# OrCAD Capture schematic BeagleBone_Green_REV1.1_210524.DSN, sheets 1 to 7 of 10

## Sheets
1 P01_Title Page: title: BeagleBone Green Cover Page; rev: v1
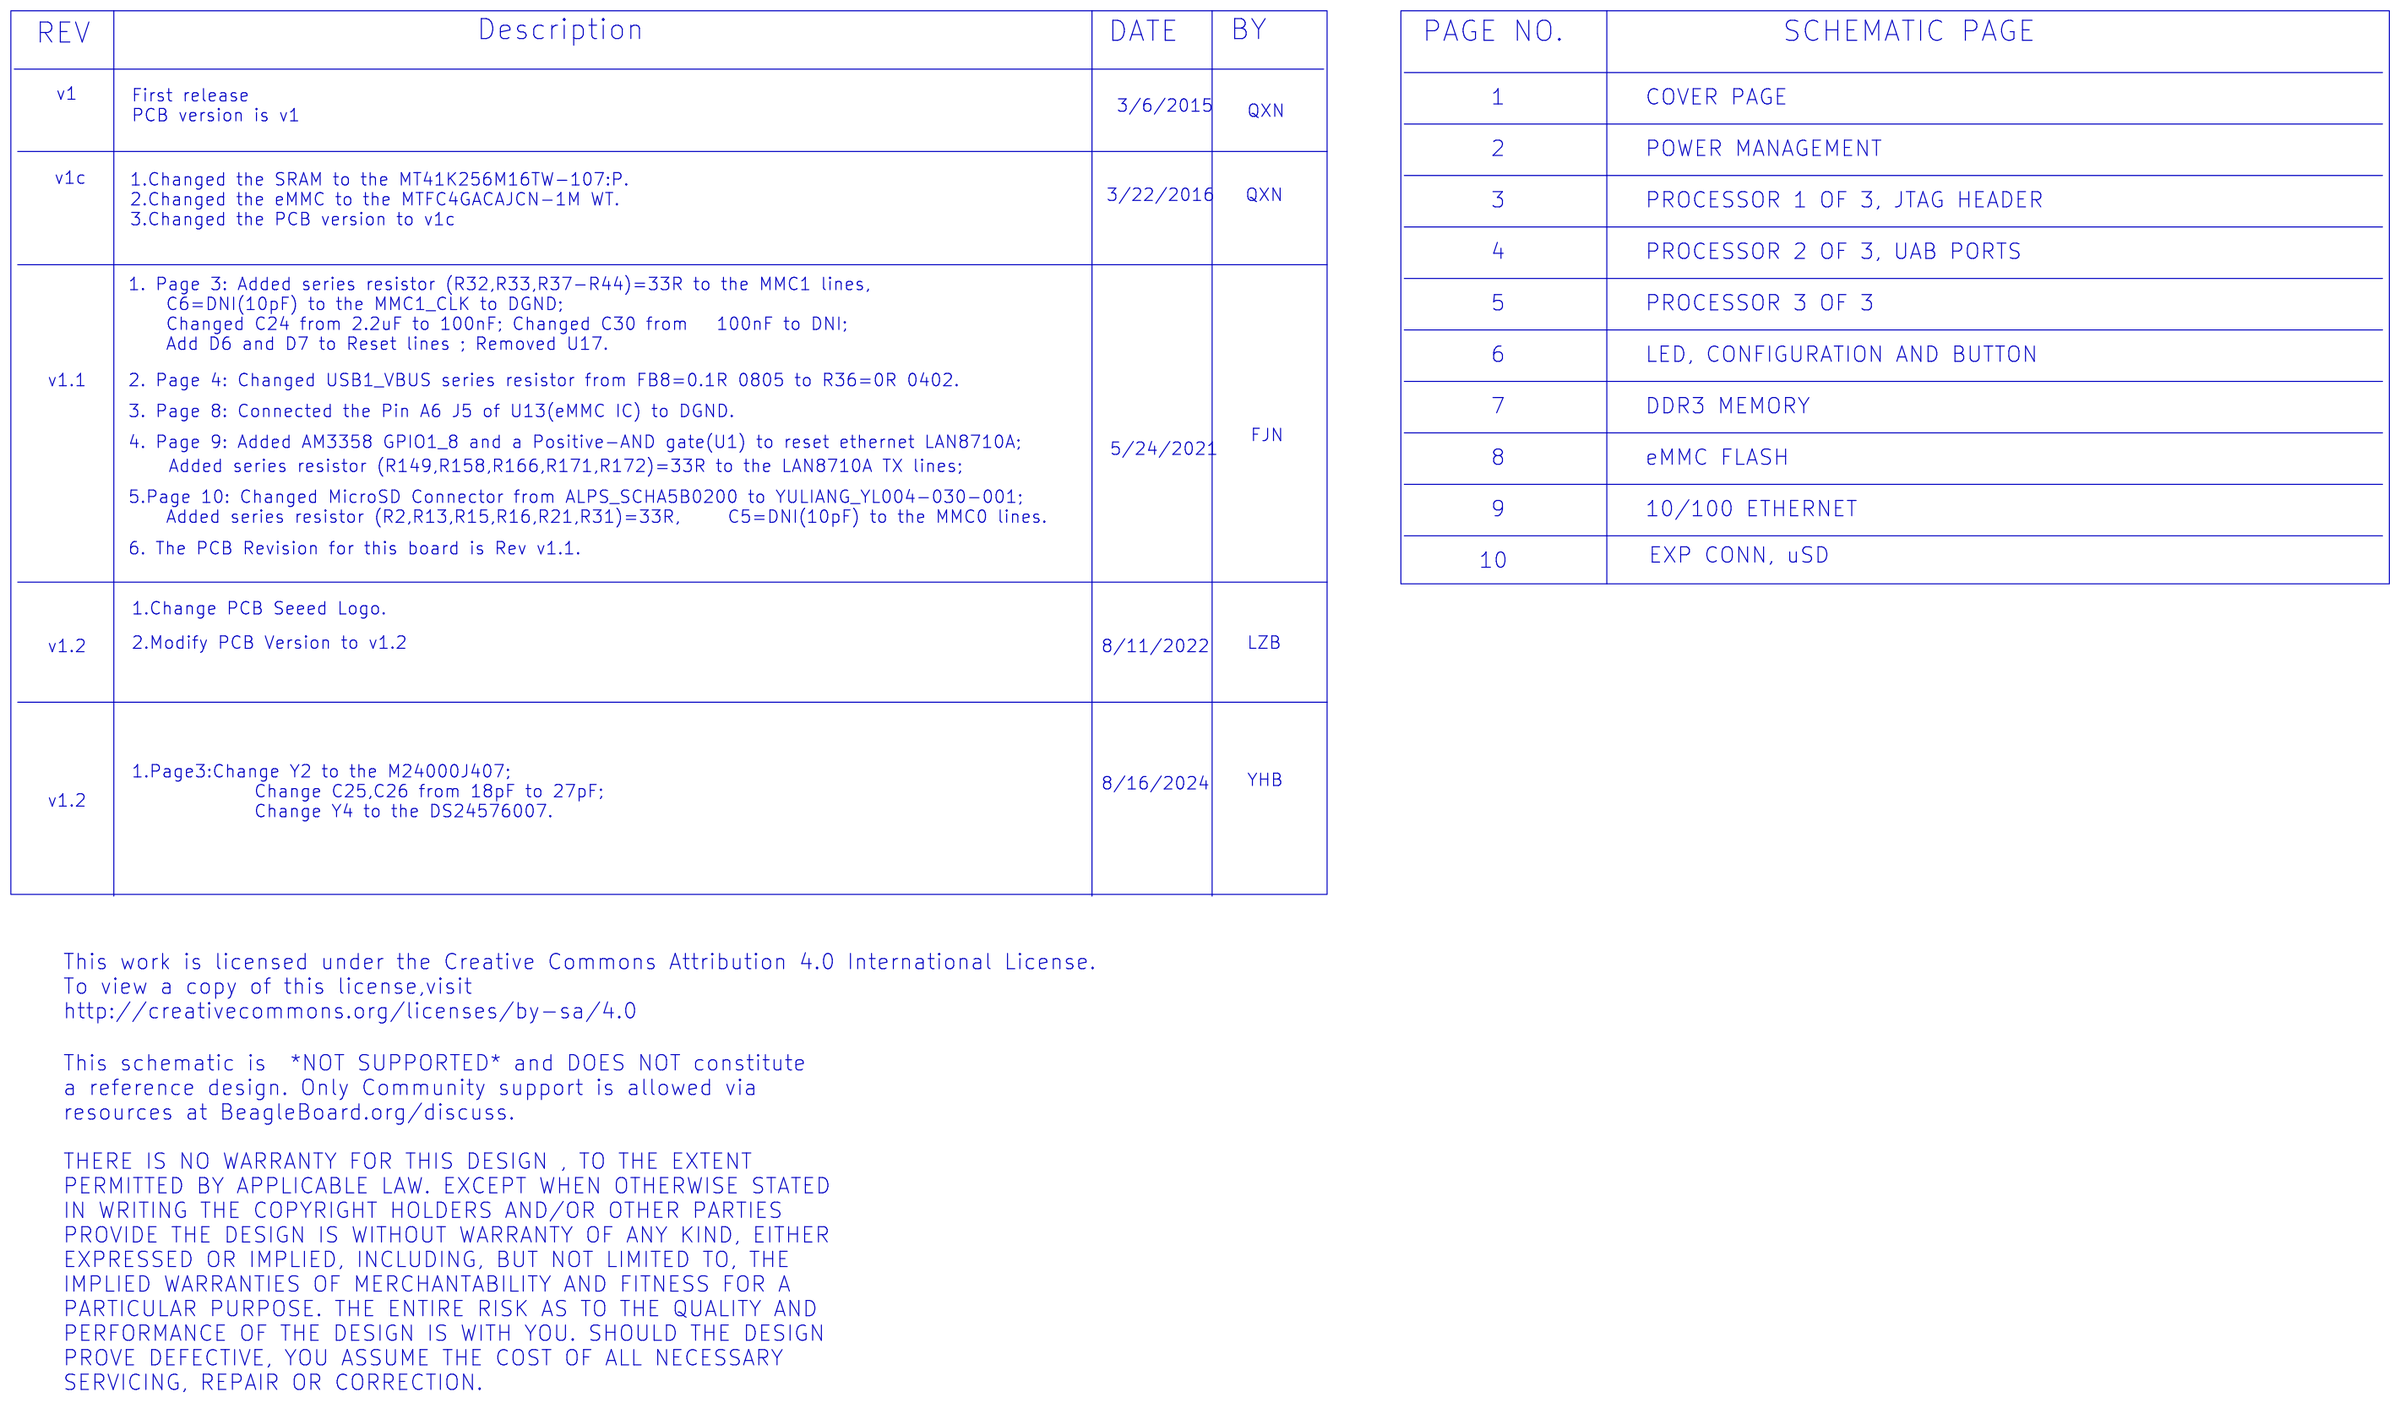
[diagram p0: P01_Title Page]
2 P02_Power Management: size B; title: BeagleBone Green Power Management
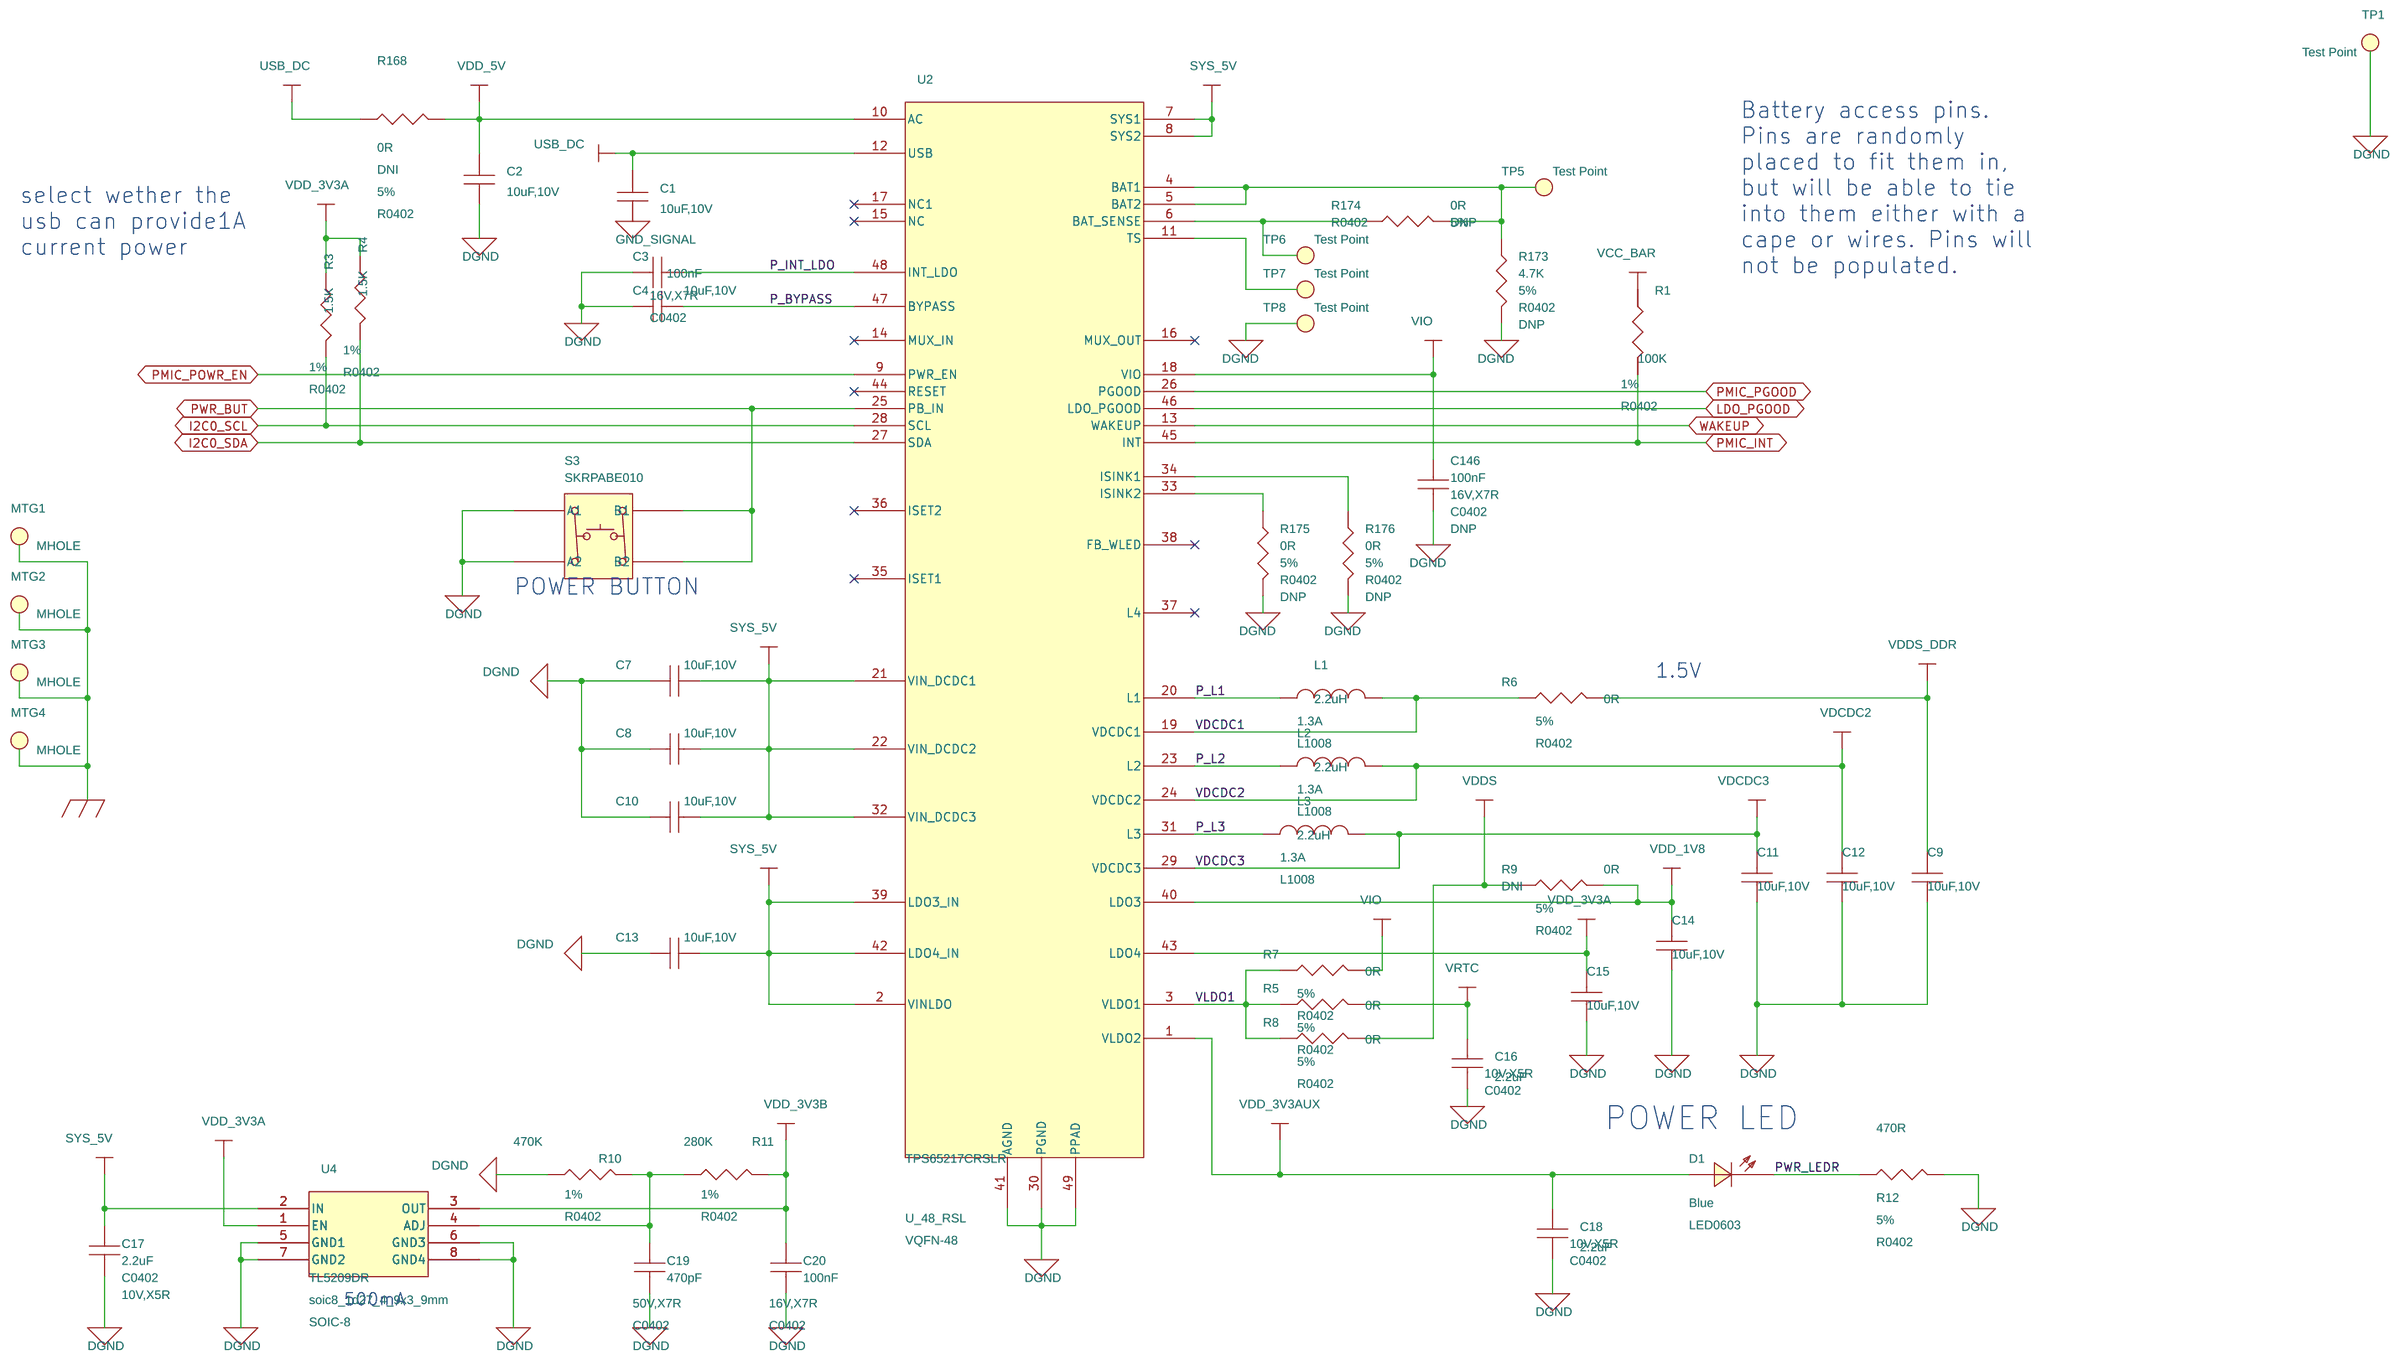
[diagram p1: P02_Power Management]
3 P06_LED, Config: size B; title: BeagleBone Green LED, Configuration, and Reset
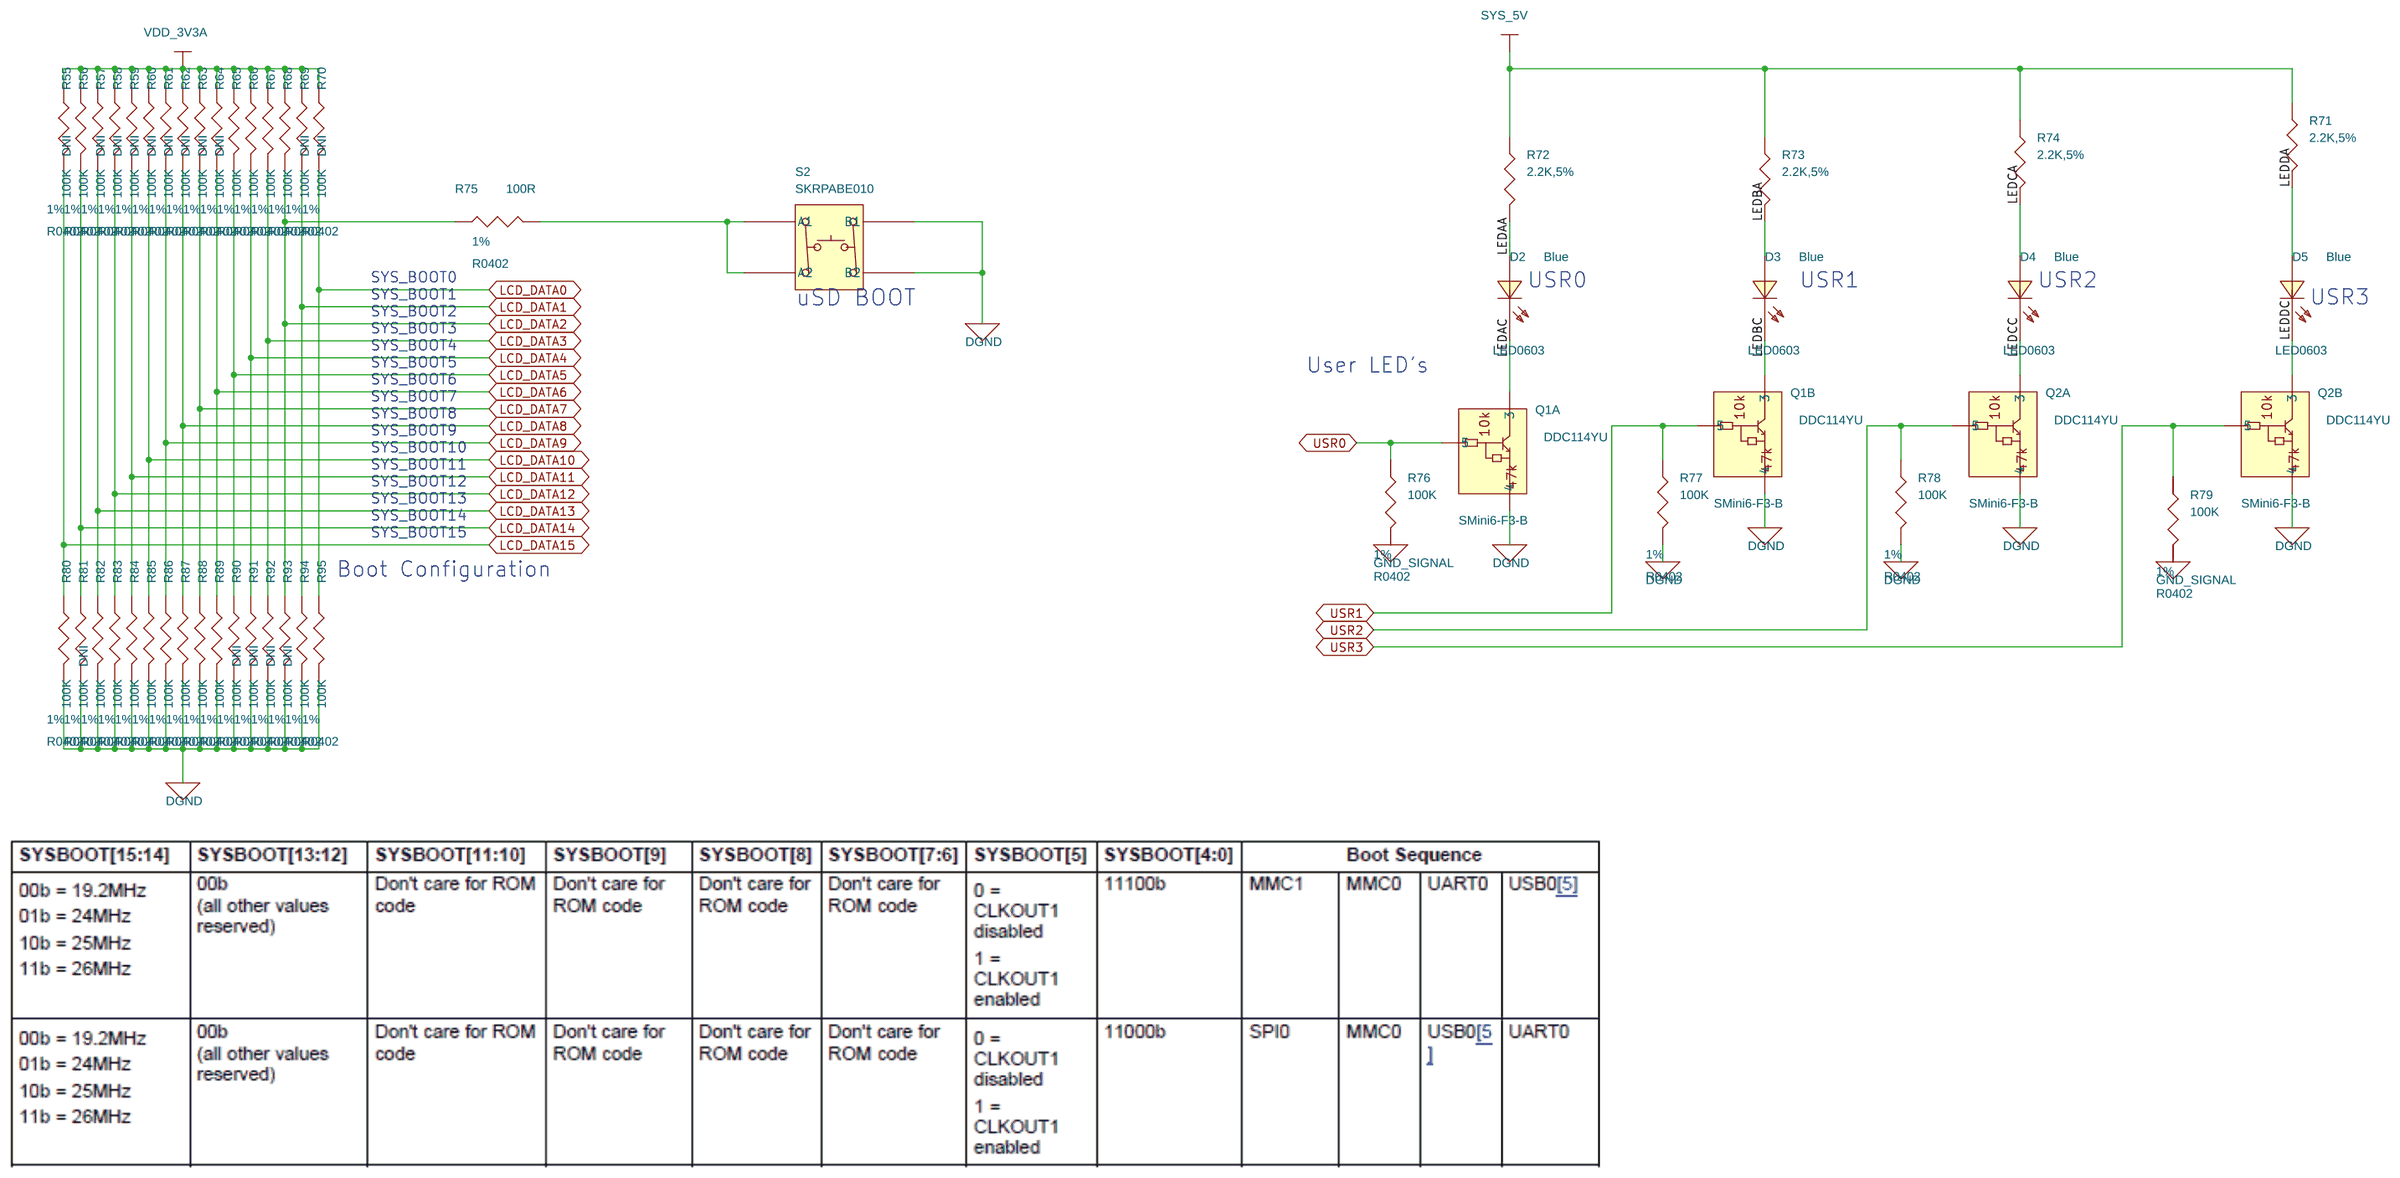
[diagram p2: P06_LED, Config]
4 P07_DDR3 Memory: size B; title: BeagleBone Green DDR3 Memory
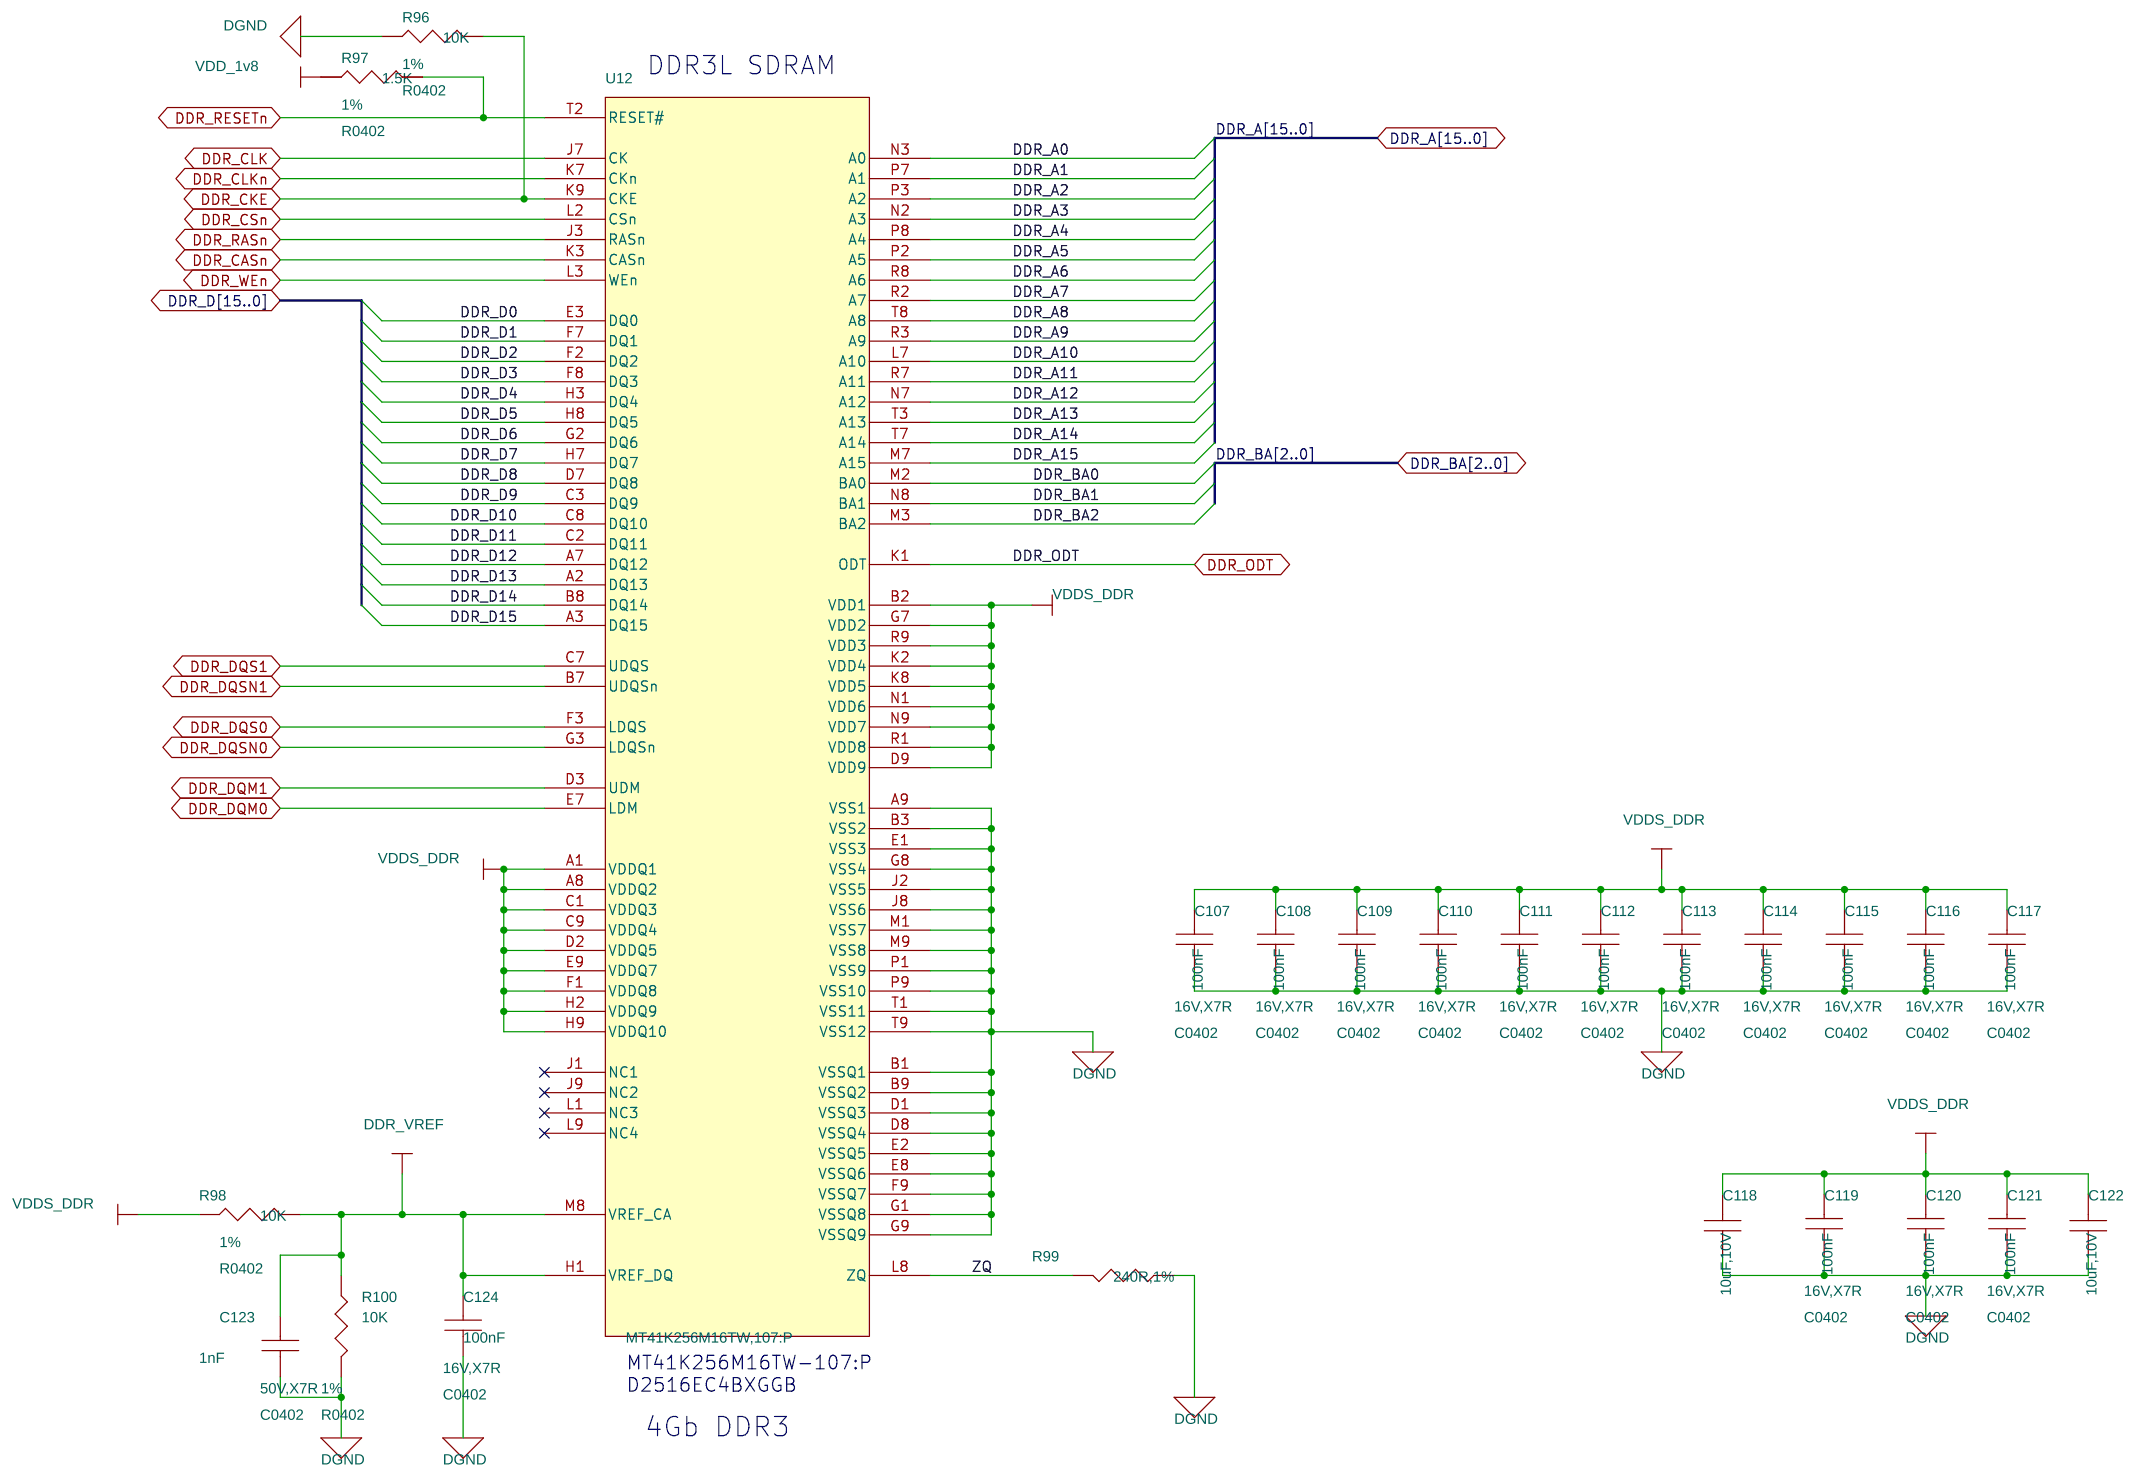
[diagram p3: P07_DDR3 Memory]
5 P08_eMMC FLASH: size B; title: BeagleBone Green 4G eMMC
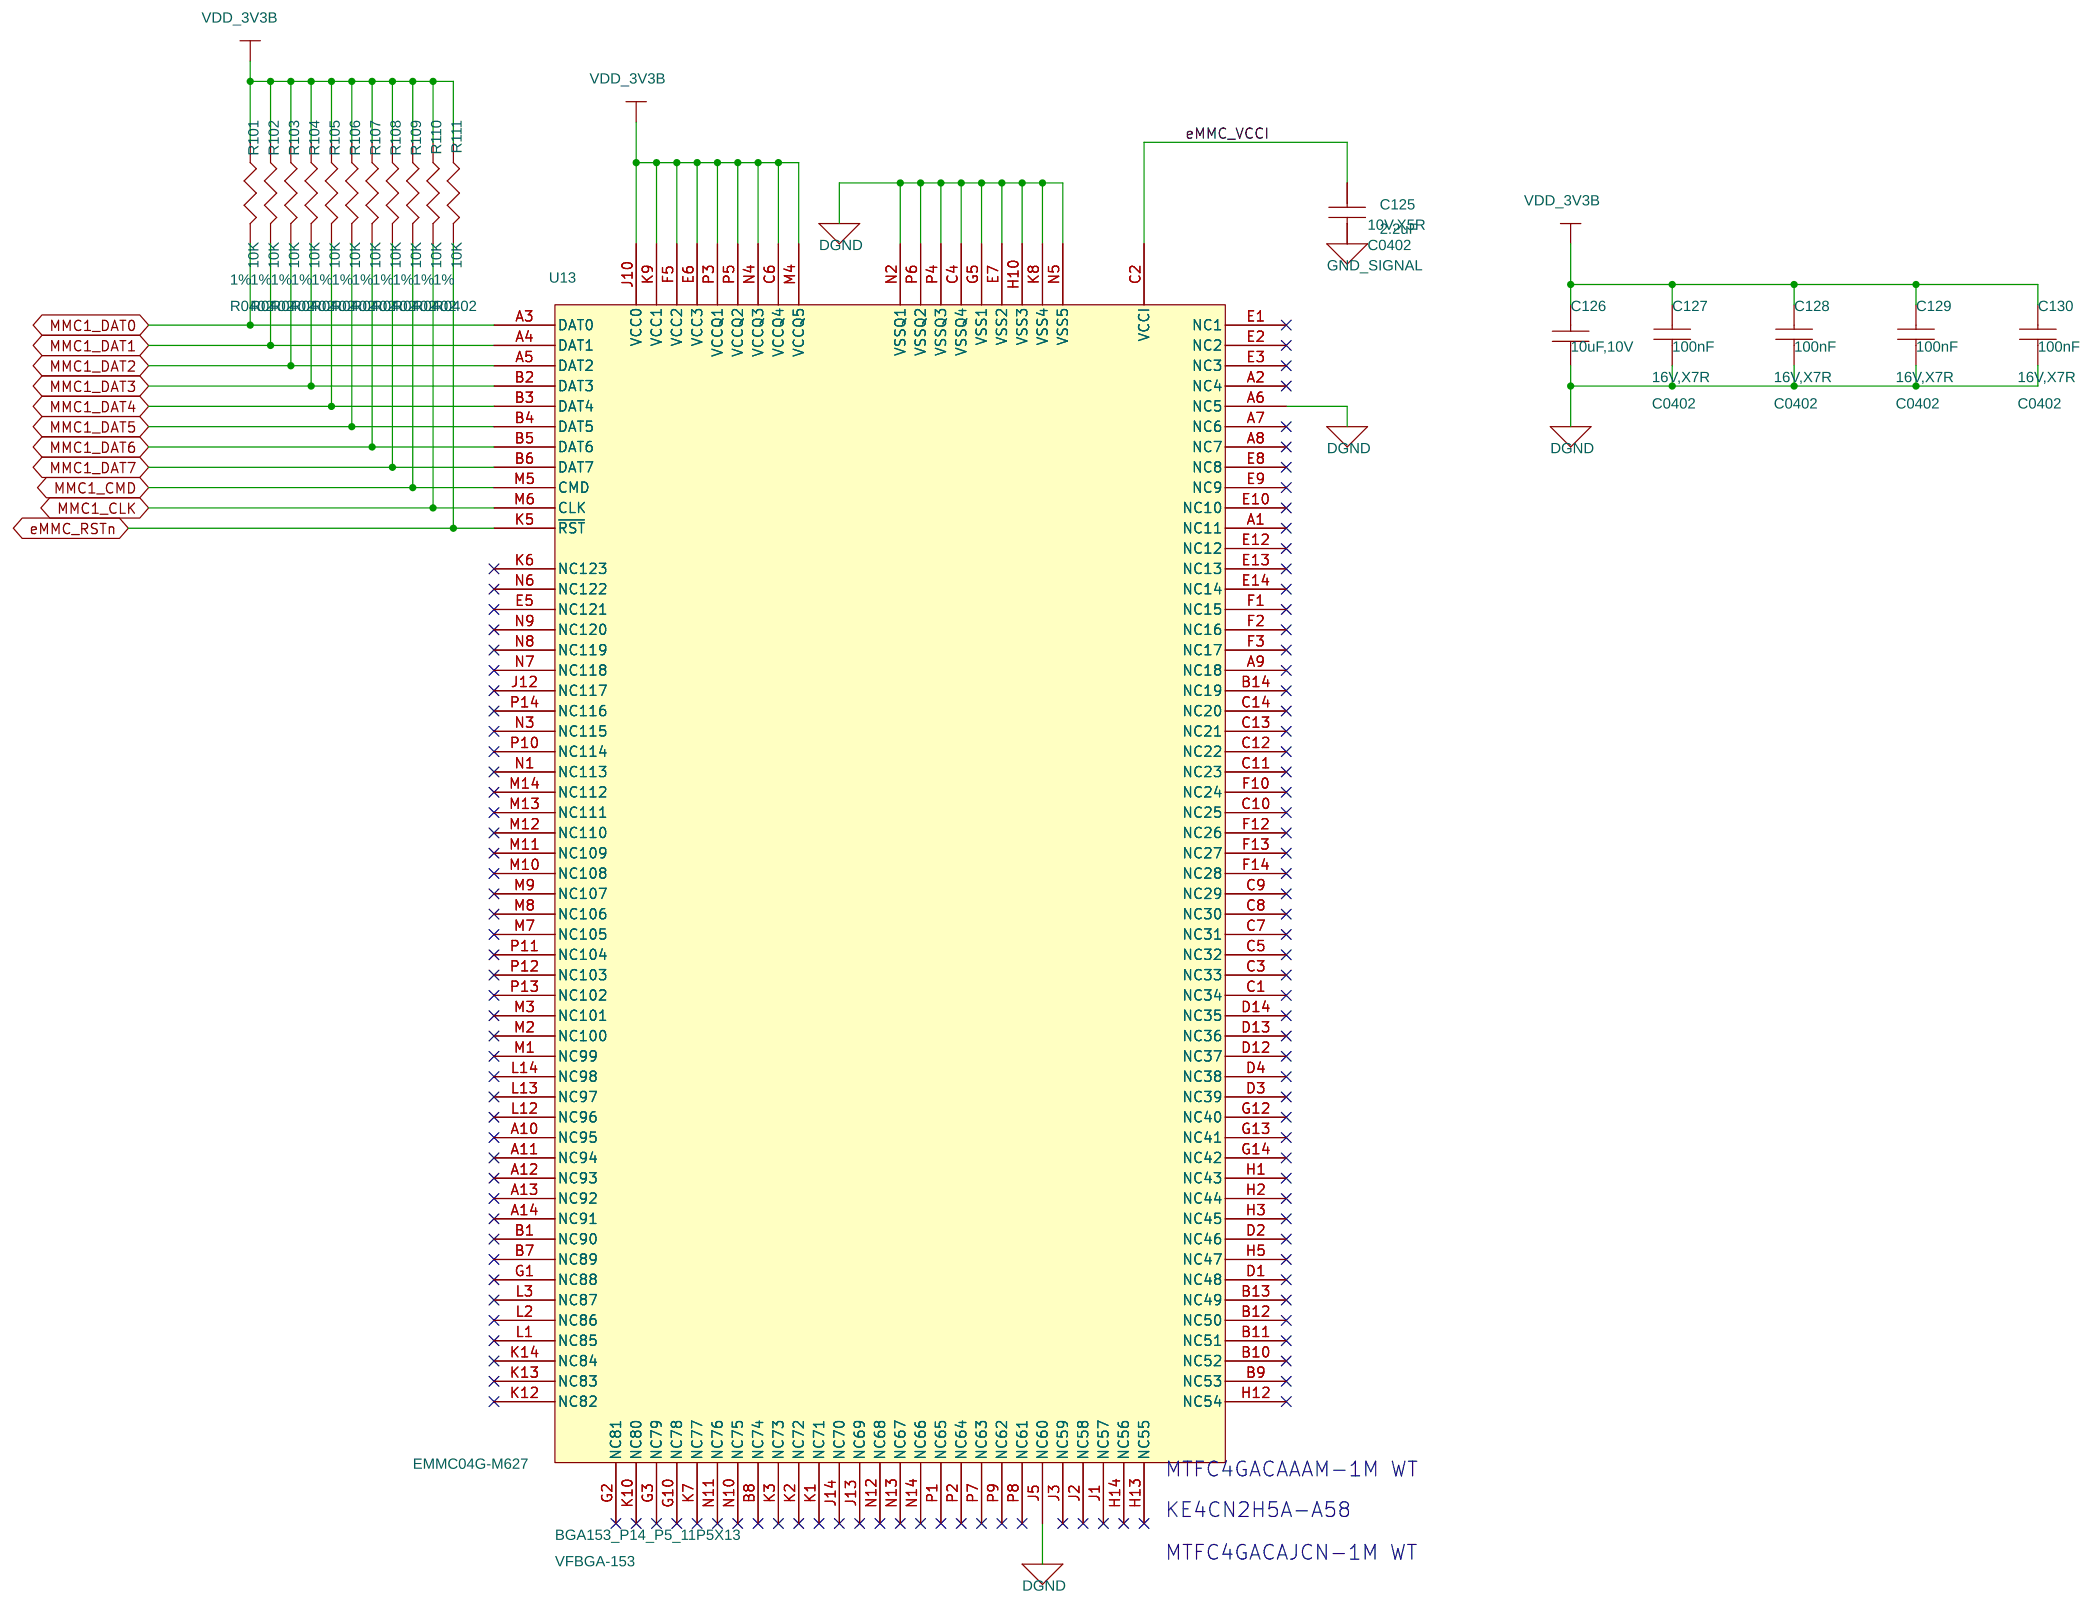
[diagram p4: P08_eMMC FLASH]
6 P10_Exp Conn, uSD: size B; title: BeagleBone Green Expansion Headers, uSD.and EEPROM
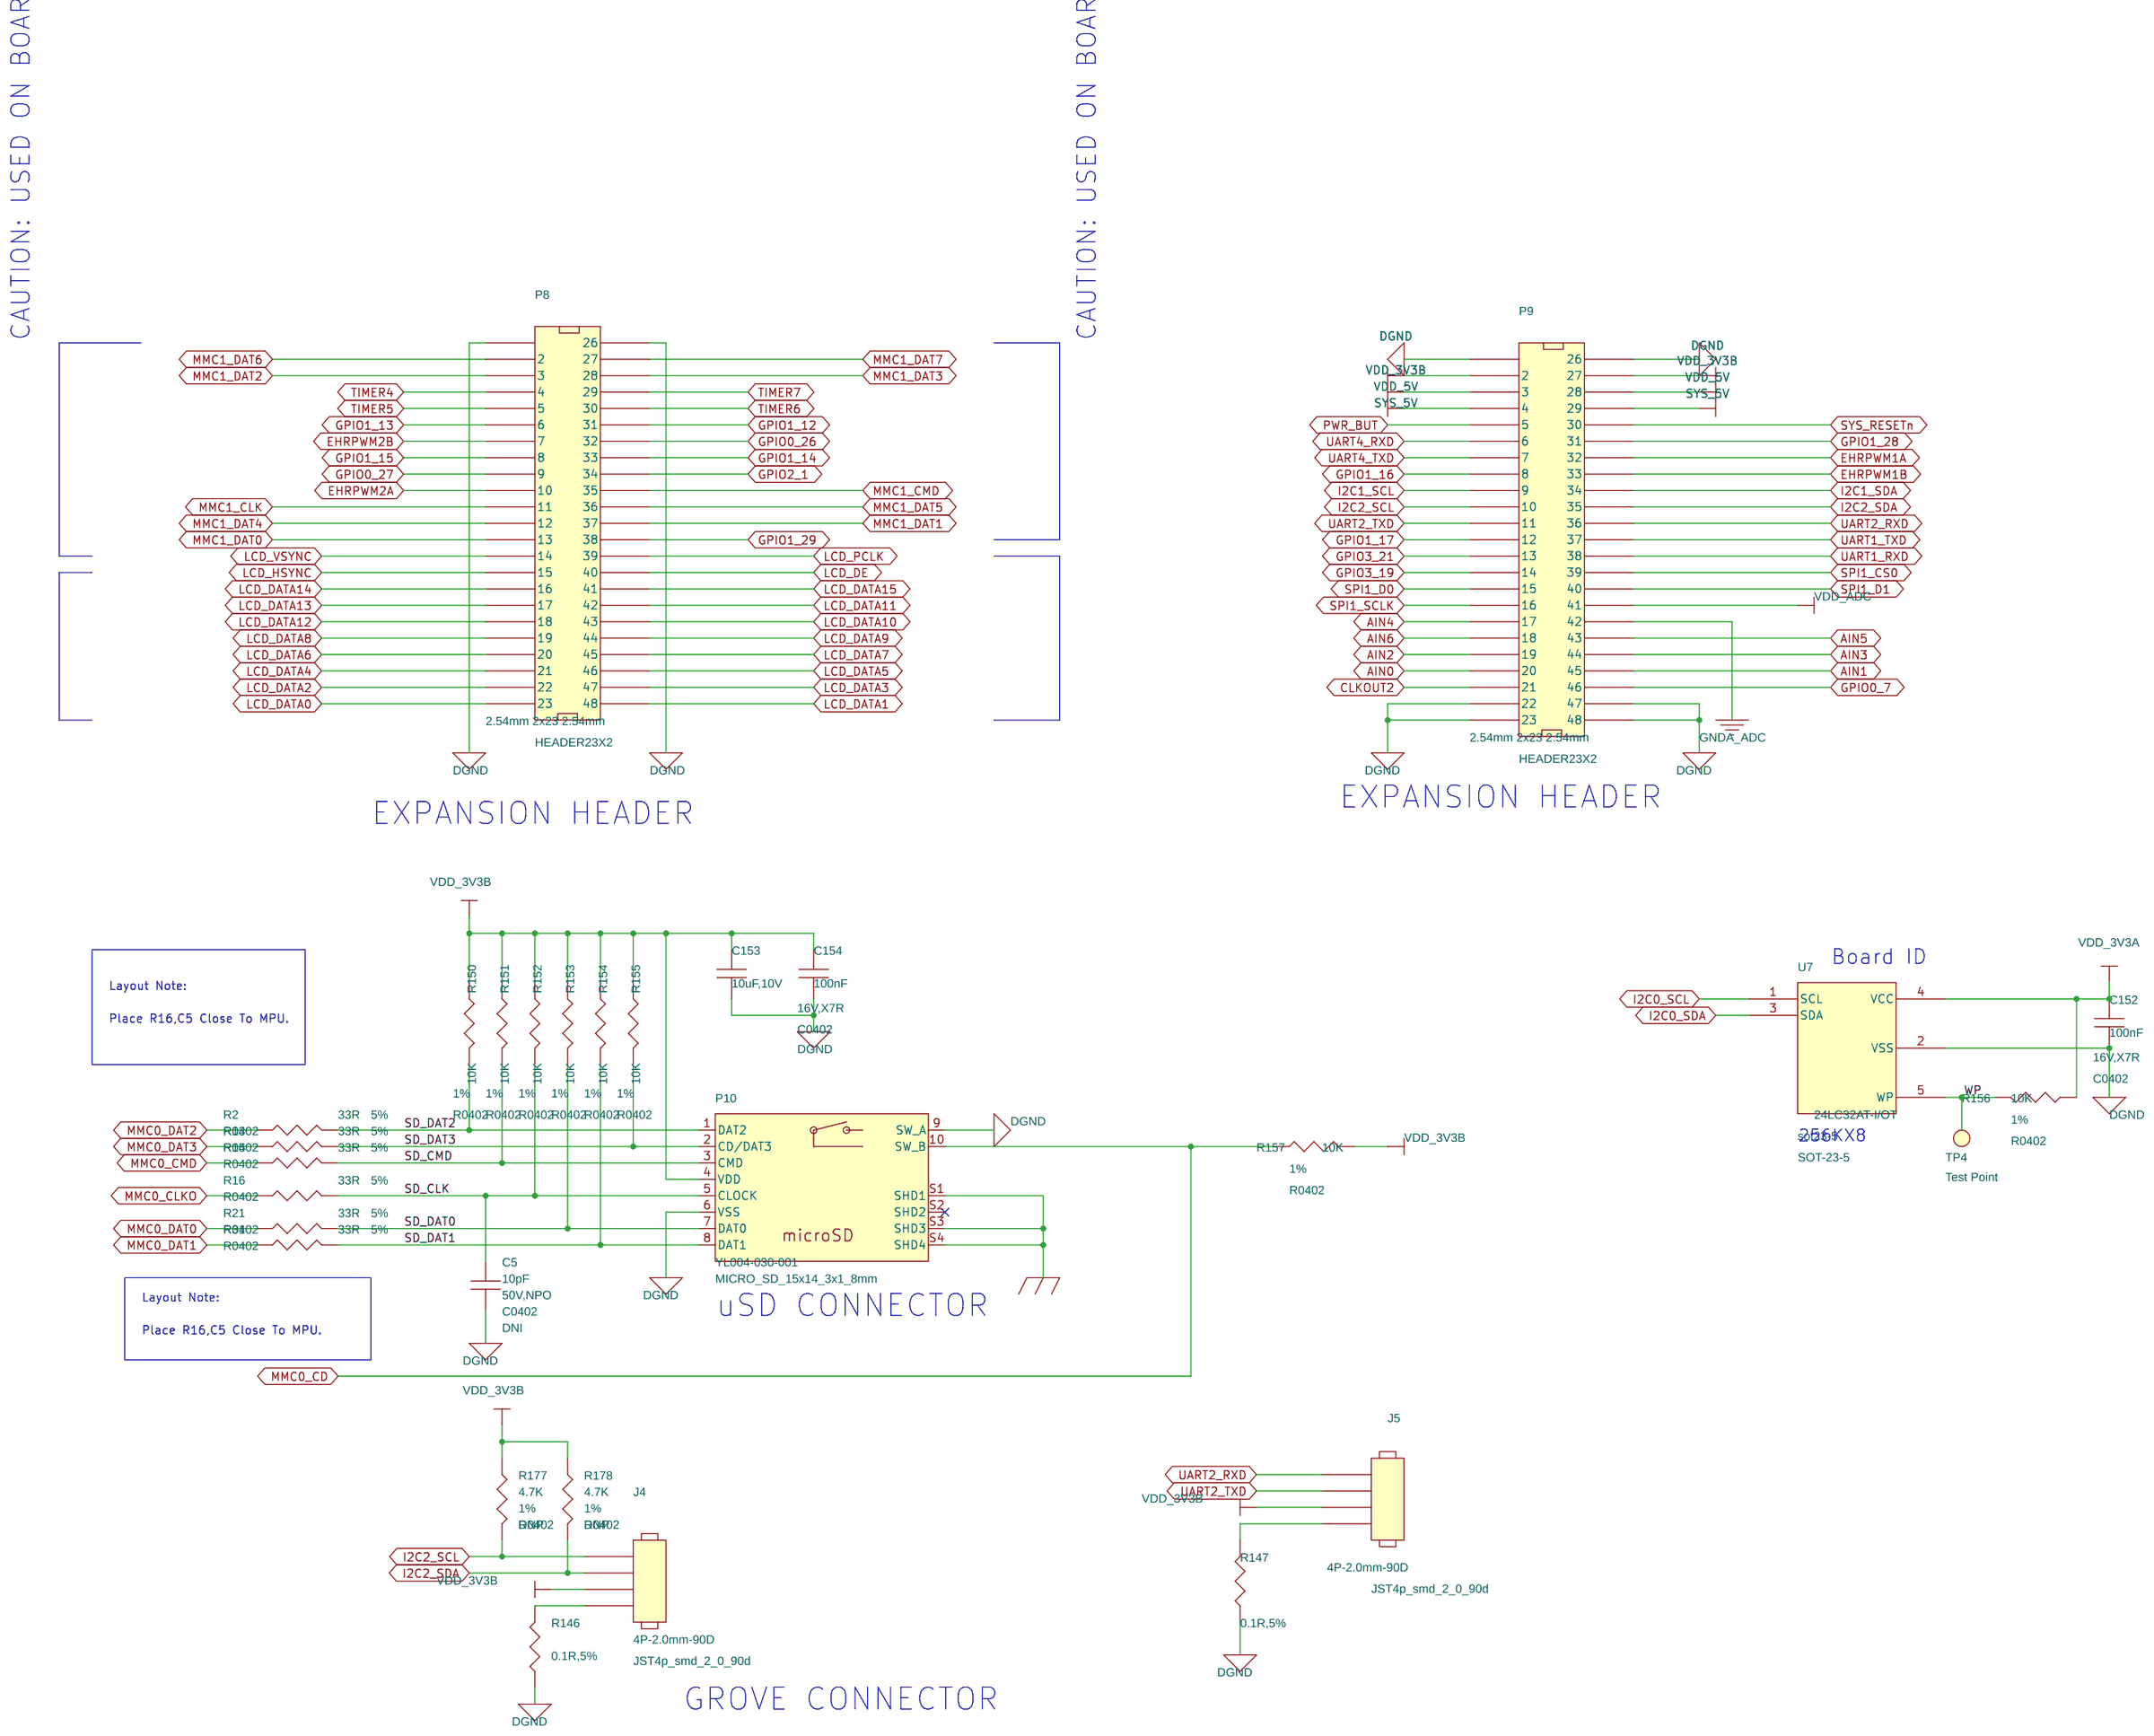
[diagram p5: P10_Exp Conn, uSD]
7 P05_AM335x 3/3: size C; title: BeagleBone Green Processr 3 of 3
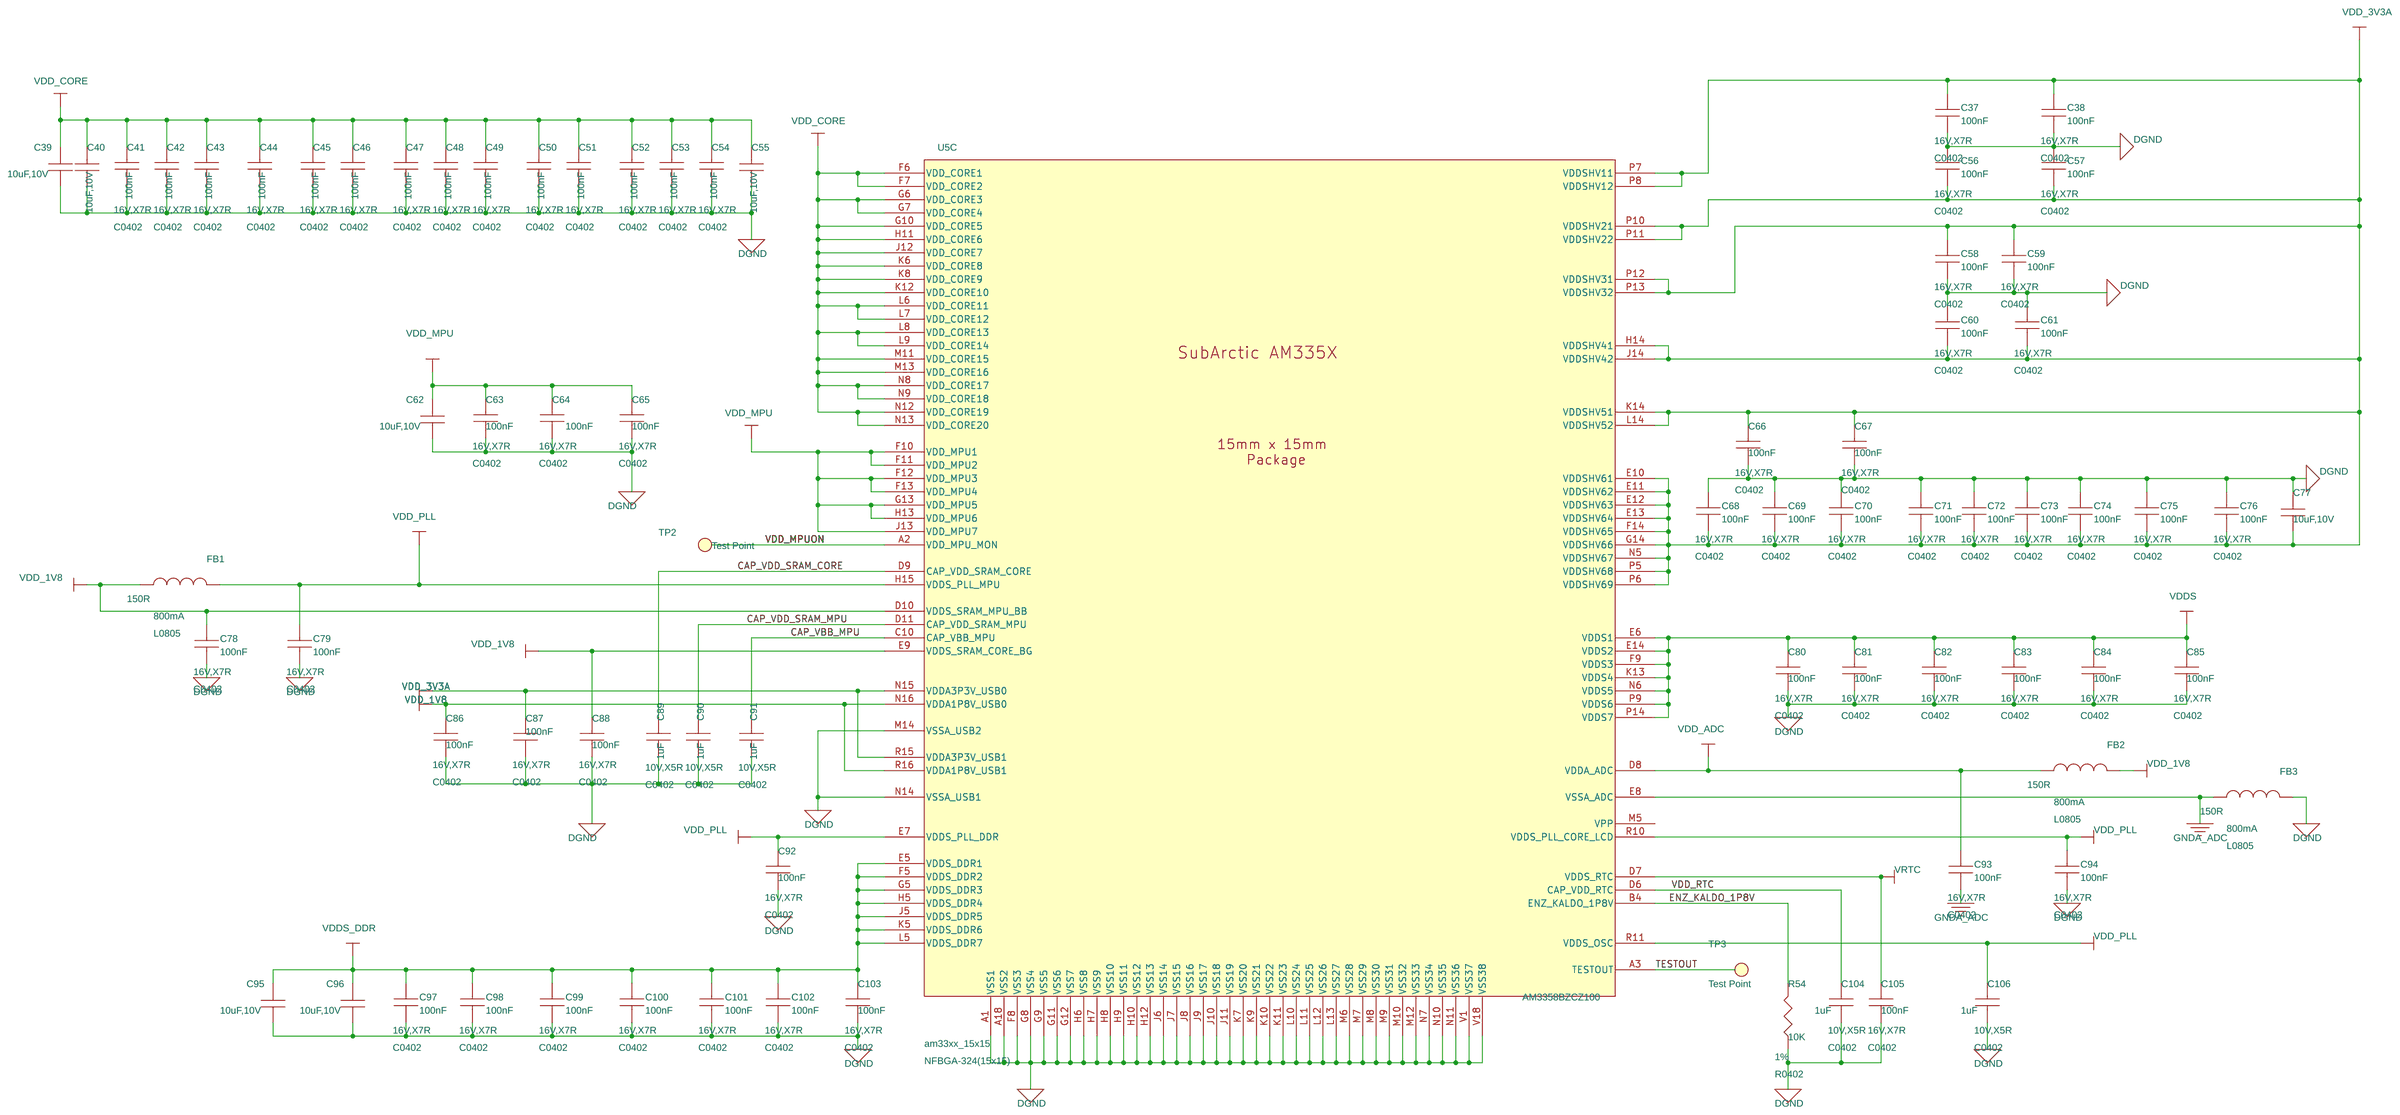
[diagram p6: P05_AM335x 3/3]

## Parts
sheet P02_Power Management
C1  10uF,10V  [805]
C2  10uF,10V  [805]
C3  100nF  [C0402]
C4  10uF,10V  [805]
C7  10uF,10V  [805]
C8  10uF,10V  [805]
C9  10uF,10V  [805]
C10  10uF,10V  [805]
C11  10uF,10V  [805]
C12  10uF,10V  [805]
C13  10uF,10V  [805]
C14  10uF,10V  [805]
C15  10uF,10V  [805]
C16  2.2uF  [C0402]
C17  2.2uF  [C0402]
C18  2.2uF  [C0402]
C19  470pF  [C0402]
C20  100nF  [C0402]
C146  100nF  [C0402]
D1  Blue  [LED0603]
L1  2.2uH  [L1008]
L2  2.2uH  [L1008]
L3  2.2uH  [L1008]
MTG1  MHOLE  [MTGH200C125D_PL]
MTG2  MHOLE  [MTGH200C125D_PL]
MTG3  MHOLE  [MTGH200C125D_PL]
MTG4  MHOLE  [MTGH200C125D_PL]
R1  100K  [R0402]
R3  1.5K  [R0402]
R4  1.5K  [R0402]
R5  0R  [R0402]
R6  0R  [R0402]
R7  0R  [R0402]
R8  0R  [R0402]
R9  0R  [R0402]
R10  470K  [R0402]
R11  280K  [R0402]
R12  470R  [R0402]
R168  0R  [R0402]
R173  4.7K  [R0402]
R174  0R  [R0402]
R175  0R  [R0402]
R176  0R  [R0402]
S3  SKRPABE010  [SW_4P]
TP1  Test Point  [tp1-8040]
TP5  Test Point  [TP60C33D]
TP6  Test Point  [TP60C33D]
TP7  Test Point  [TP60C33D]
TP8  Test Point  [TP60C33D]
U2  TPS65217CRSLR  [U_48_RSL]
U4  TL5209DR  [soic8_1d27_4_9x3_9mm]
sheet P04_AM335x 2/3, USB
U5  AM3358BZCZ100  [am33xx_15x15]  (sections A,B,C)
sheet P05_AM335x 3/3
C37  100nF  [C0402]
C38  100nF  [C0402]
C39  10uF,10V  [805]
C40  10uF,10V  [805]
C41  100nF  [C0402]
C42  100nF  [C0402]
C43  100nF  [C0402]
C44  100nF  [C0402]
C45  100nF  [C0402]
C46  100nF  [C0402]
C47  100nF  [C0402]
C48  100nF  [C0402]
C49  100nF  [C0402]
C50  100nF  [C0402]
C51  100nF  [C0402]
C52  100nF  [C0402]
C53  100nF  [C0402]
C54  100nF  [C0402]
C55  10uF,10V  [805]
C56  100nF  [C0402]
C57  100nF  [C0402]
C58  100nF  [C0402]
C59  100nF  [C0402]
C60  100nF  [C0402]
C61  100nF  [C0402]
C62  10uF,10V  [805]
C63  100nF  [C0402]
C64  100nF  [C0402]
C65  100nF  [C0402]
C66  100nF  [C0402]
C67  100nF  [C0402]
C68  100nF  [C0402]
C69  100nF  [C0402]
C70  100nF  [C0402]
C71  100nF  [C0402]
C72  100nF  [C0402]
C73  100nF  [C0402]
C74  100nF  [C0402]
C75  100nF  [C0402]
C76  100nF  [C0402]
C77  10uF,10V  [805]
C78  100nF  [C0402]
C79  100nF  [C0402]
C80  100nF  [C0402]
C81  100nF  [C0402]
C82  100nF  [C0402]
C83  100nF  [C0402]
C84  100nF  [C0402]
C85  100nF  [C0402]
C86  100nF  [C0402]
C87  100nF  [C0402]
C88  100nF  [C0402]
C89  1uF  [C0402]
C90  1uF  [C0402]
C91  1uF  [C0402]
C92  100nF  [C0402]
C93  100nF  [C0402]
C94  100nF  [C0402]
C95  10uF,10V  [805]
C96  10uF,10V  [805]
C97  100nF  [C0402]
C98  100nF  [C0402]
C99  100nF  [C0402]
C100  100nF  [C0402]
C101  100nF  [C0402]
C102  100nF  [C0402]
C103  100nF  [C0402]
C104  1uF  [C0402]
C105  100nF  [C0402]
C106  1uF  [C0402]
FB1  150R  [L0805]
FB2  150R  [L0805]
FB3  150R  [L0805]
R54  10K  [R0402]
TP2  Test Point  [TP60C_SMD]
TP3  Test Point  [TP60C_SMD]
sheet P06_LED, Config
D2  Blue  [LED0603]
D3  Blue  [LED0603]
D4  Blue  [LED0603]
D5  Blue  [LED0603]
Q1  DDC114YU  [SMini6-F3-B]  (sections A,B)
Q2  DDC114YU  [SMini6-F3-B]  (sections A,B)
R55  100K  [R0402]
R56  100K  [R0402]
R57  100K  [R0402]
R58  100K  [R0402]
R59  100K  [R0402]
R60  100K  [R0402]
R61  100K  [R0402]
R62  100K  [R0402]
R63  100K  [R0402]
R64  100K  [R0402]
R65  100K  [R0402]
R66  100K  [R0402]
R67  100K  [R0402]
R68  100K  [R0402]
R69  100K  [R0402]
R70  100K  [R0402]
R71  2.2K,5%  [402]
R72  2.2K,5%  [402]
R73  2.2K,5%  [402]
R74  2.2K,5%  [402]
R75  100R  [R0402]
R76  100K  [R0402]
R77  100K  [R0402]
R78  100K  [R0402]
R79  100K  [R0402]
R80  100K  [R0402]
R81  100K  [R0402]
R82  100K  [R0402]
R83  100K  [R0402]
R84  100K  [R0402]
R85  100K  [R0402]
R86  100K  [R0402]
R87  100K  [R0402]
R88  100K  [R0402]
R89  100K  [R0402]
R90  100K  [R0402]
R91  100K  [R0402]
R92  100K  [R0402]
R93  100K  [R0402]
R94  100K  [R0402]
R95  100K  [R0402]
S2  SKRPABE010  [SW_4P]
sheet P07_DDR3 Memory
C107  100nF  [C0402]
C108  100nF  [C0402]
C109  100nF  [C0402]
C110  100nF  [C0402]
C111  100nF  [C0402]
C112  100nF  [C0402]
C113  100nF  [C0402]
C114  100nF  [C0402]
C115  100nF  [C0402]
C116  100nF  [C0402]
C117  100nF  [C0402]
C118  10uF,10V  [805]
C119  100nF  [C0402]
C120  100nF  [C0402]
C121  100nF  [C0402]
C122  10uF,10V  [805]
C123  1nF  [C0402]
C124  100nF  [C0402]
R96  10K  [R0402]
R97  1.5K  [R0402]
R98  10K  [R0402]
R99  240R,1%  [SM-7351-RES-0402]
R100  10K  [R0402]
U12  MT41K256M16TW,107:P  [BGA96_T9_P8_9X14]
sheet P08_eMMC FLASH
C125  2.2uF  [C0402]
C126  10uF,10V  [805]
C127  100nF  [C0402]
C128  100nF  [C0402]
C129  100nF  [C0402]
C130  100nF  [C0402]
R101  10K  [R0402]
R102  10K  [R0402]
R103  10K  [R0402]
R104  10K  [R0402]
R105  10K  [R0402]
R106  10K  [R0402]
R107  10K  [R0402]
R108  10K  [R0402]
R109  10K  [R0402]
R110  10K  [R0402]
R111  10K  [R0402]
U13  EMMC04G-M627  [BGA153_P14_P5_11P5X13]
sheet P10_Exp Conn, uSD
C5  10pF  [C0402]
C152  100nF  [C0402]
C153  10uF,10V  [805]
C154  100nF  [C0402]
J4  4P-2.0mm-90D  [JST4p_smd_2_0_90d]
J5  4P-2.0mm-90D  [JST4p_smd_2_0_90d]
P8  2.54mm 2x23 2.54mm  [HEADER23X2]
P9  2.54mm 2x23 2.54mm  [HEADER23X2]
P10  YL004-030-001  [MICRO_SD_15x14_3x1_8mm]
R2  33R  [R0402]
R13  33R  [R0402]
R15  33R  [R0402]
R16  33R  [R0402]
R21  33R  [R0402]
R31  33R  [R0402]
R146  0.1R,5%  [805]
R147  0.1R,5%  [805]
R150  10K  [R0402]
R151  10K  [R0402]
R152  10K  [R0402]
R153  10K  [R0402]
R154  10K  [R0402]
R155  10K  [R0402]
R156  10K  [R0402]
R157  10K  [R0402]
R177  4.7K  [R0402]
R178  4.7K  [R0402]
TP4  Test Point  [tp1-8040]
U7  24LC32AT-I/OT  [sot23-5]

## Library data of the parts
C1 C2 C4 C7-C15 C39 C40 C55 C62 C77 C95 C96 C118 C122 C126 C153 = CAP_10uF_Y5V_10V_10%_0805: SMD CAP Ceramic 10uF-10V-(-20%~+80%)-Y5V;0805; Manufacturer: YAGEO; Manufacturer Part Number: CC0805ZKY5V6BB106; PN: 302010158; Part Type: Ceramic Capacitor; Rating: 10V,Y5V; Temperature: -30C to 85C
C3 C20 C37 C38 C41-C54 C56-C61 C63-C76 C78-C88 C92-C94 C97-C103 C105 C107-C117 C119-C121 C124 C127-C130 C152 C154 = CAP_0.1uF_X5R_6.3V_20%_0201: SMD CAP Ceramic 100nF-16V-10%-X7R;0402; Manufacturer: YAGEO; Manufacturer Part Number: CC0402KRX7R7BB104; PN: 302010004; Package Size: 0402; Part Type: Ceramic Capacitor; Rating: 16V,X7R; Status: BeagleBone Carrier Board; Temperature: -55°C to 125°C
C16-C18 C125 = CC: SMD CAP Ceramic 2.2uF-10V-10%-X5R;0402; Manufacturer: YAGEO; Manufacturer Part Number: CC0402KRX5R6BB225; PN: 302012819; Package Size: 0402; Part Type: Ceramic; Rating: 10V,X5R; Status: BBG; Temperature: -55°C to 85°C
C19 = CAP_470PF_X7R_25V_10%_0402: SMD CAP Ceramic 470pF-50V-10%-X7R;0402; Manufacturer: YAGEO; Manufacturer Part Number: CC0402KRX7R9BB471; PN: 302010010; Package Size: 0402; Part Type: Ceramic Capacitor; Rating: 50V,X7R; Status: Mini-Gateway; Temperature: -55°C to 125°C
C146 = CC: SMD CAP Ceramic 100nF-16V-10%-X7R;0402; ASSY: DNP; Manufacturer: YAGEO; Manufacturer Part Number: CC0402KRX7R7BB104; PN: 302010004; Package Size: 0402; Part Type: Ceramic; Rating: 16V,X7R; Status: BeagleBone Carrier Board; Temperature: -55°C to 125°C
D1-D5 = LED_LTST-C150GKT_0: SMD LED Clear-Blue;0603; Manufacturer: Everlight; Manufacturer Part Number: 19-217/BHC-ZL1M2RY/6T; PN: 304090045; Package Size: 0603; Part Type: Diode TVS; Status: BeagleBone Carrier Board; Temperature: -40°C to 85°C
L1-L3 = IND_2.2uH_2.6A_10%_SMD: SMD Inductor 2.2uH-20%-1.3A;2P-2520; Manufacturer: Murata; Manufacturer Part Number: LQM2HPN2R2MG0L; PN: 303010128; Package Size: 2520; Part Type: Inductor; Rating: 1.3A; Status: Combox Pro; Temperature: -55°C to 125°C
MTG1-MTG4 = MHOLE: Plated Hole,125mil,175mil; ASSY: DNI; Part Type: Plated Hole
R1 R56 R65-R68 R76-R80 R82-R89 R94 R95 = RES_100K_1_16W_1%_0402: SMD RES 100K-1%-1/16W;0402; Manufacturer: YAGEO; Manufacturer Part Number: RC0402FR-07100KL; PN: 301010456; Package Size: 0402; Part Type: Thick Film Resistor; Rating: 1%; Status: BeagleBone Carrier Board; Temperature: -55°C to 155°C
R3 R4 = RES_1.5K_1_16W_5%_0402: SMD RES 1.5K-1%-1/16W;0402; Manufacturer: YAGEO; Manufacturer Part Number: RC0402FR-071K5L; PN: 301010567; Package Size: 0402; Part Type: Thick Film Resistor; Rating: 1%; Status: BeagleBone Carrier Board; Temperature: -55°C to 155°C
R5-R8 = RES_4.75K_1_16W_1%_0402: SMD RES 0R-5%-1/16W;0402; Manufacturer: YAGEO; Manufacturer Part Number: RC0402JR-070RL; PN: 301010000; Package Size: 0402; Part Type: Thick Film Resistor; Rating: 5%; Status: BeagleBone Carrier Board; Temperature: -55°C to 155°C
R9 = RES_4.75K_1_16W_1%_0402: SMD RES 0R-5%-1/16W;0402; ASSY: DNI; Manufacturer: YAGEO; Manufacturer Part Number: RC0402JR-070RL; PN: 301010000; Package Size: 0402; Part Type: Thick Film Resistor; Rating: 5%; Status: BeagleBone Carrier Board; Temperature: -55°C to 155°C
R10 = RES_470_1_10W_5%_0402: SMD RES 470K-1%-1/16W;0402; Manufacturer: YAGEO; Manufacturer Part Number: RC0402FR-07470KL; PN: 301010069; Package Size: 0402; Part Type: Thick Film Resistor; Rating: 1%; Status: Combox Pro; Temperature: -55°C to 155°C
R11 = RES_470_1_10W_5%_0402: SMD RES;280K-1%-1/16W-0402; Manufacturer: YAGEO; Manufacturer Part Number: RC0402FR-07280KL; PN: 301010642; Package Size: 0402; Part Type: Thick Film Resistor; Rating: 1%; Status: Combox Pro; Temperature: -55°C to 155°C
R12 = RES_470_1_10W_5%_0402: SMD RES 470R-5%-1/16W;0402; Manufacturer: YAGEO; Manufacturer Part Number: RC0402JR-07470RL; PN: 301010013; Package Size: 0402; Part Type: Thick Film Resistor; Rating: 5%; Status: BeagleBone AI TDA4VM; Temperature: -55°C to 155°C
R168 = RES_1.5K_1_16W_5%_0402: SMD RES 0R-5%-1/16W;0402; ASSY: DNI; Manufacturer: YAGEO; Manufacturer Part Number: RC0402JR-070RL; PN: 301010000; Package Size: 0402; Part Type: Thick Film Resistor; Rating: 5%; Status: BeagleBone Carrier Board; Temperature: -55°C to 155°C
R173 = R: SMD RES 4.7K-5%-1/16W;0402; ASSY: DNP; Manufacturer: YAGEO; Manufacturer Part Number: RC0402JR-074K7L; PN: 301010010; Package Size: 0402; Part Type: RES; Rating: 5%; Status: BeagleBone Carrier Board; Temperature: -55°C to 155°C
R174-R176 = R: SMD RES 0R-5%-1/16W;0402; ASSY: DNP; Manufacturer: YAGEO; Manufacturer Part Number: RC0402JR-070RL; PN: 301010000; Package Size: 0402; Part Type: RES; Rating: 5%; Status: BeagleBone Carrier Board; Temperature: -55°C to 155°C; Datasheet: Y:\01_Cadence_Library\05_Datasheet\301010000_YAGEO_RC0402JR-070RL_Datasheet.pdf
S3 = SW_KT11P2JM_2: SMD Top Button 1.57N;4P-L4.6*W3.2*H2.5mm; Manufacturer: ALPS; PN: 311020518; Part Type: Button; Temperature: -30C to 85C
TP1 TP4 = TESTPT1: DIP Test Point,40mil,60mil; ASSY: DNI
TP5-TP8 = TESTPT1: DIP Test Point,35mil,60mil; ASSY: DNI
U2 = PWR_TPS65217_2: SMD IC PMIC;VQFN-48; Manufacturer: TI; PN: 310030209; Package Size: VQFN-48; Part Type: PMIC; Status: Combox Pro; Temperature: -40°C to 105°C
U4 = PWR_TLV70233DBV_0: SMD IC PMIC;LDO-ADJ-500mA;SOIC-8; Manufacturer: TI; PN: 310030210; Package Size: SOIC-8; Part Type: LDO; Status: Combox Pro
U5 = IC_AM335X_ZCZ: SMD IC MCU;NFBGA-324（15x15）; Manufacturer: TI; PN: 310010099; Package Size: NFBGA-324(15x15); Part Type: MPU; Status: Combox Pro; Temperature: 0°C to 90°C
C89-C91 C104 C106 = CAP_1.0UF_X5R_10V_10%_0402: SMD CAP Ceramic 1uF-10V-10%-X5R;0402; Manufacturer: YAGEO; Manufacturer Part Number: CC0402KRX5R6BB105; PN: 302010040; Package Size: 0402; Part Type: Ceramic Capacitor; Rating: 10V,X5R; Status: BeagleBone Carrier Board; Temperature: -55°C to 85°C
FB1-FB3 = FER_180_200_0: SMD Ferrite Bead;150R-800mA-0805; Manufacturer: LAIRD; Manufacturer Part Number: LI0805H151R-10; PN: 303030029; Package Size: 0805; Part Type: Ferrite Bead; Rating: 800mA; Status: BeagleBone Green Gateway; Temperature: -40°C to 125°C
R54 R96 R98 R100-R111 R150-R155 R157 = RES_10K_1_16W_1%_0402: SMD RES 10K-1%-1/16W;0402; Manufacturer: YAGEO; Manufacturer Part Number: RC0402FR-0710KL; PN: 301010047; Package Size: 0402; Part Type: Thick Film Resistor; Rating: 1%; Status: BeagleBone Carrier Board; Temperature: -55°C to 155°C
TP2 TP3 = TESTPT1: SMD Test Point,50mil,Circle; ASSY: DNI
Q1 Q2 = RN1907: SMD Transistor Array 2 NPN-50V-100mA-SOT-363; ATLStockNo2: 2130.01; Manufacturer: Diodes; Manufacturer Part Number: DDC114YU-7-F; PN: 305050004; Package Size: SOT-363; Part Type: Transistor NPN; Status: BeagleBone Carrier Board; Temperature: -55°C to 155°C
R55 R57-R64 R69 R70 R81 R90-R93 = RES_100K_1_16W_1%_0402: SMD RES 100K-1%-1/16W;0402; ASSY: DNI; Manufacturer: YAGEO; Manufacturer Part Number: RC0402FR-07100KL; PN: 301010456; Package Size: 0402; Part Type: Thick Film Resistor; Rating: 1%; Status: BeagleBone Carrier Board; Temperature: -55°C to 155°C
R71-R74 = RES_470_1_10W_5%_0402: SMD RES 2.2K-5%-1/16W;0402; Manufacturer: YAGEO; Manufacturer Part Number: RC0402JR-072K2L; PN: 301010039; Part Type: Thick Film Resistor; Rating: 0.05; Temperature: -55C to 155C
R75 = RES_100K_1_16W_1%_0402: SMD RES 100R-1%-1/16W;0402; Manufacturer: YAGEO; Manufacturer Part Number: RC0402FR-07100RL; PN: 301010442; Package Size: 0402; Part Type: Thick Film Resistor; Rating: 1%; Status: BeagleBone Carrier Board; Temperature: -55°C to 155°C
S2 = SW_KT11P2JM_1: SMD Top Button 1.57N;4P-L4.6*W3.2*H2.5mm; Manufacturer: ALPS; PN: 311020518; Part Type: Button; Temperature: -30C to 85C
C123 = CAP_0.001_X7R_50V_5%_0402: SMD CAP Ceramic 1nF-50V-10%-X7R;0402; Manufacturer: YAGEO; Manufacturer Part Number: CC0402KRX7R9BB102; PN: 302010005; Package Size: 0402; Part Type: Ceramic Capacitor; Rating: 50V,X7R; Status: RT-M7; Temperature: -55°C to 125°C
R97 = RES_10K_1_16W_1%_0402: SMD RES 1.5K-1%-1/16W;0402; Manufacturer: YAGEO; Manufacturer Part Number: RC0402FR-071K5L; PN: 301010567; Package Size: 0402; Part Type: Thick Film Resistor; Rating: 1%; Status: BeagleBone Carrier Board; Temperature: -55°C to 155°C
R99 = Res: SMD RES;240R-1%-0402; Created By: Sankar; Created Date: 4/12/2010; DescriptiveText: RES 240 OHM 1/10W 1% 0402 SMD; Manufacturer: Panasonic; Manufacturer Part Number: ERJ-2RKF2400X; Mfg: KOA; Mfr: Panasonic-ECG; MfrNum: ERJ-2RKF2400X; PN: 301010494; Part Type: Thick Film Resistor; PartName: 240E1/10W1%smd0402; Rating: 0.01; Sub_Type: Thick Film; Temperature: -55C to 155C; Tolerance: 1%
U12 = MT47H256M8_7: SMD IC Memory;TFBGA-96(8x14); DescriptiveText: DDR3 Memory 4Gb; Manufacturer: Micron; Manufacturer Part Number: MT41K256M16TW-107:P; Mfr: Micron; MfrNum: MT41J256M16RE-15E; PN: 310091066; Part Type: DDR3L; PartName: MT41J256M16RE-15E; Temperature: 0C to 95C
U13 = MEM_MNAND_2GB: SMD IC Memory;VFBGA-153; Manufacturer: Kingston; PN: 310090564; Package Size: VFBGA-153; Part Type: eMMC; Status: BeagleBone Carrier Board; Temperature: -25°C to 85°C
C5 = CC: SMD CAP Ceramic 10pF-50V-5%-NPO;0402; ASSY: DNI; Manufacturer: YAGEO; Manufacturer Part Number: CC0402JRNPO9BN100; PN: 302010001; Package Size: 0402; Part Type: Ceramic; Rating: 50V,NPO; Status: BeagleBone Carrier Board; Temperature: -55°C to 125°C
J4 J5 = HEADER_4: SMD Grove Female Header-Beige;4P-2.0-90D; Manufacturer: SINOTOP Electronics; Manufacturer Part Number: HY2.0-A 90D SMD; PN: 320110032; Package Size: 4P-2.0-90D; Part Type: Header; Status: Eagleye 310s
P8 P9 = HDR_46_F_2_0.1_0.1: DIP Black Female Header;2*23P-2.54*8.5-3.0mm; Manufacturer: SINOTOP Electronics; Manufacturer Part Number: FF-1236; PN: 320030424; Package Size: 2*23P-2.54*8.5-3.0mm; Part Type: Header; Status: BeagleBone Carrier Board
P10 = MicroSD_Card_10+4P: SMD SD Card Holder;Reverse-Bottom,8P-14.3*16mm; Manufacturer: Yuliang Electronics; PN: 320090416; Package Size: 4P+6-L15*W14*H1.8mm; Part Type: SD Card; Status: SeeedStudio BeagleBone Black; Temperature: -20°C to 85°C
R2 R13 R15 R16 R21 R31 = R: SMD RES 33R-5%-1/16W;0402; Manufacturer: YAGEO; Manufacturer Part Number: RC0402JR-0733RL; PN: 301010034; Package Size: 0402; Part Type: RES; Rating: 5%; Status: BeagleBone Carrier Board; Temperature: -55°C to 155°C
R146 R147 = RES_0.1_0805: SMD RES 0.1R-5%-1/8W;0805; Manufacturer: YAGEO; Manufacturer Part Number: RL0805JR-070R1L; PN: 301010264; Part Type: Thick Film Resistor; Rating: 0.05; Temperature: -55C to 155C
R156 = RES_0_1_16W_1%_0402: SMD RES 10K-1%-1/16W;0402; Manufacturer: YAGEO; Manufacturer Part Number: RC0402FR-0710KL; PN: 301010047; Package Size: 0402; Part Type: Thick Film Resistor; Rating: 1%; Status: BeagleBone Carrier Board; Temperature: -55°C to 155°C
R177 R178 = R: SMD RES;4.7K-1%-1/16W-0402; ASSY: DNP; Manufacturer: YAGEO; Manufacturer Part Number: RC0402FR-074K7L; PN: 301010633; Package Size: 0402; Part Type: RES; Rating: 1%; Status: BeagleBone Carrier Board; Temperature: -55°C to 155°C
U7 = MEM_24LC32_SOT23-5: SMD IC Memory;SOT-23-5; Manufacturer: Microchip; PN: 310090051; Package Size: SOT-23-5; Part Type: EEPROM; Status: Testo PoE; Temperature: -40°C to 85°C

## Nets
DGND: C1.1 C2.1 C3.1 C4.1 C5.2 C7.1 C8.1 C9.1 C10.1 C11.1 C12.1 C13.1 C14.1 C15.1 C16.2 C17.2 C18.2 C19.2 C20.2 C37.2 C38.2 C39.1 C40.1 C41.2 C42.2 C43.2 C44.2 C45.2 C46.2 C47.2 C48.2 C49.2 C50.2 C51.2 C52.2 C53.2 C54.2 C55.1 C56.1 C57.1 C58.2 C59.2 C60.1 C61.1 C62.1 C63.2 C64.2 C65.2 C66.2 C67.2 C68.1 C69.1 C70.1 C71.1 C72.1 C73.1 C74.1 C75.1 C76.1 C77.2 C78.2 C79.2 C80.2 C81.2 C82.2 C83.2 C84.2 C85.2 C86.2 C87.2 C88.2 C89.2 C90.2 C91.2 C92.2 C94.2 C95.1 C96.1 C97.2 C98.2 C99.2 C100.2 C101.2 C102.2 C103.2 C104.2 C105.2 C106.2 C107.2 C108.2 C109.2 C110.2 C111.2 C112.2 C113.2 C114.2 C115.2 C116.2 C117.2 C118.1 C119.2 C120.2 C121.2 C122.1 C123.2 C124.2 C125.2 C126.1 C127.2 C128.2 C129.2 C130.2 C146.2 C152.2 C153.2 C154.2 FB3.2 P8.1 P8.2(26) P9.1 P9.2(26) P9.43(22) P9.44(47) P9.45(23) P9.46(48) P10.6(VSS) P10.9(SW_A) Q1.1(4) Q1.4 Q2.1(4) Q2.4 R10.2 R12.1 R54.1 R76.2 R77.2 R78.2 R79.2 R80.2 R81.2 R82.2 R83.2 R84.2 R85.2 R86.2 R87.2 R88.2 R89.2 R90.2 R91.2 R92.2 R93.2 R94.2 R95.2 R96.1 R99.1 R100.2 R146.1 R147.1 R173.2 R175.2 R176.2 S2.2(B1) S2.4(B2) S3.1(A1) S3.3(A2) TP1.1(TP) TP8.1(TP) U2.30(PGND) U2.41(AGND) U2.49(PPAD) U4.5(GND1) U4.6(GND3) U4.7(GND2) U4.8(GND4) U5.A1(VSS1) U5.A18(VSS2) U5.F8(VSS3) U5.G8(VSS4) U5.G9(VSS5) U5.G11(VSS6) U5.G12(VSS7) U5.H6(VSS8) U5.H7(VSS9) U5.H8(VSS10) U5.H9(VSS11) U5.H10(VSS12) U5.H12(VSS13) U5.J6(VSS14) U5.J7(VSS15) U5.J8(VSS16) U5.J9(VSS17) U5.J10(VSS18) U5.J11(VSS19) U5.K7(VSS20) U5.K9(VSS21) U5.K10(VSS22) U5.K11(VSS23) U5.L10(VSS24) U5.L11(VSS25) U5.L12(VSS26) U5.L13(VSS27) U5.M6(VSS28) U5.M7(VSS29) U5.M8(VSS30) U5.M9(VSS31) U5.M10(VSS32) U5.M12(VSS33) U5.M14(VSSA_USB2) U5.N7(VSS34) U5.N10(VSS35) U5.N11(VSS36) U5.N14(VSSA_USB1) U5.V1(VSS37) U5.V18(VSS38) U7.2(VSS) U12.A9(VSS1) U12.B1(VSSQ1) U12.B3(VSS2) U12.B9(VSSQ2) U12.D1(VSSQ3) U12.D8(VSSQ4) U12.E1(VSS3) U12.E2(VSSQ5) U12.E8(VSSQ6) U12.F9(VSSQ7) U12.G1(VSSQ8) U12.G8(VSS4) U12.G9(VSSQ9) U12.J2(VSS5) U12.J8(VSS6) U12.M1(VSS7) U12.M9(VSS8) U12.P1(VSS9) U12.P9(VSS10) U12.T1(VSS11) U12.T9(VSS12) U13.A6(NC5) U13.C4(VSSQ4) U13.E7(VSS2) U13.G5(VSS1) U13.H10(VSS3) U13.J5(NC60) U13.K8(VSS4) U13.N2(VSSQ1) U13.N5(VSS5) U13.P4(VSSQ3) U13.P6(VSSQ2) ; also on sheet 8 9 10
GND_EARTH: MTG1.1(TP) MTG2.1(TP) MTG3.1(TP) MTG4.1(TP) P10.S1(SHD1) P10.S3(SHD3) P10.S4(SHD4) ; also on sheet 8 9
GNDA_ADC: C93.2 FB3.1 P9.34(42) U5.E8(VSSA_ADC) ; also on sheet 9
VDD_1V8: C14.2 C78.1 C86.1 C88.1 FB1.1 FB2.2 R9.2 U2.40(LDO3) U5.D10(VDDS_SRAM_MPU_BB) U5.E9(VDDS_SRAM_CORE_BG) U5.N16(VDDA1P8V_USB0) U5.R16(VDDA1P8V_USB1)
VDD_3V3A: C15.2 C37.1 C38.1 C56.2 C57.2 C58.1 C59.1 C60.2 C61.2 C66.1 C67.1 C68.2 C69.2 C70.2 C71.2 C72.2 C73.2 C74.2 C75.2 C76.2 C77.1 C87.1 C152.1 R1.1 R3.1 R4.1 R55.1 R56.1 R57.1 R58.1 R59.1 R60.1 R61.1 R62.1 R63.1 R64.1 R65.1 R66.1 R67.1 R68.1 R69.1 R70.1 R156.1 U2.43(LDO4) U4.1(EN) U5.E10(VDDSHV61) U5.E11(VDDSHV62) U5.E12(VDDSHV63) U5.E13(VDDSHV64) U5.F14(VDDSHV65) U5.G14(VDDSHV66) U5.H14(VDDSHV41) U5.J14(VDDSHV42) U5.K14(VDDSHV51) U5.L14(VDDSHV52) U5.N5(VDDSHV67) U5.N15(VDDA3P3V_USB0) U5.P5(VDDSHV68) U5.P6(VDDSHV69) U5.P7(VDDSHV11) U5.P8(VDDSHV12) U5.P10(VDDSHV21) U5.P11(VDDSHV22) U5.P12(VDDSHV31) U5.P13(VDDSHV32) U5.R15(VDDA3P3V_USB1) U7.4(VCC) ; also on sheet 9 10
VDD_3V3AUX: C18.1 D1.2(A) U2.1(VLDO2)
VDD_3V3B: C20.1 C126.2 C127.1 C128.1 C129.1 C130.1 C153.1 C154.1 J4.3 J5.3 P9.3(2) P9.4(27) P10.4(VDD) R11.1 R101.1 R102.1 R103.1 R104.1 R105.1 R106.1 R107.1 R108.1 R109.1 R110.1 R111.1 R150.1 R151.1 R152.1 R153.1 R154.1 R155.1 R157.2 R177.1 R178.1 U4.3(OUT) U13.C6(VCCQ4) U13.E6(VCC3) U13.F5(VCC2) U13.J10(VCC0) U13.K9(VCC1) U13.M4(VCCQ5) U13.N4(VCCQ3) U13.P3(VCCQ1) U13.P5(VCCQ2) ; also on sheet 8 9 10
VDD_5V: C2.2 P9.5(3) P9.6(28) R168.2 U2.10(AC)
VDD_ADC: C93.1 FB2.1 P9.32(41) U5.D8(VDDA_ADC) ; also on sheet 9
VDD_CORE: C11.2 C39.2 C40.2 C41.1 C42.1 C43.1 C44.1 C45.1 C46.1 C47.1 C48.1 C49.1 C50.1 C51.1 C52.1 C53.1 C54.1 C55.2 L3.2 U2.29(VDCDC3) U5.F6(VDD_CORE1) U5.F7(VDD_CORE2) U5.G6(VDD_CORE3) U5.G7(VDD_CORE4) U5.G10(VDD_CORE5) U5.H11(VDD_CORE6) U5.J12(VDD_CORE7) U5.K6(VDD_CORE8) U5.K8(VDD_CORE9) U5.K12(VDD_CORE10) U5.L6(VDD_CORE11) U5.L7(VDD_CORE12) U5.L8(VDD_CORE13) U5.L9(VDD_CORE14) U5.M11(VDD_CORE15) U5.M13(VDD_CORE16) U5.N8(VDD_CORE17) U5.N9(VDD_CORE18) U5.N12(VDD_CORE19) U5.N13(VDD_CORE20)
VDD_MPU: C12.2 C62.2 C63.1 C64.1 C65.1 L2.2 U2.24(VDCDC2) U5.F10(VDD_MPU1) U5.F11(VDD_MPU2) U5.F12(VDD_MPU3) U5.F13(VDD_MPU4) U5.G13(VDD_MPU5) U5.H13(VDD_MPU6) U5.J13(VDD_MPU7)
VDD_MPUON: TP2.1(TP) U5.A2(VDD_MPU_MON)
VDD_PLL: C79.1 C92.1 C94.1 C106.1 FB1.2 U5.E7(VDDS_PLL_DDR) U5.H15(VDDS_PLL_MPU) U5.R10(VDDS_PLL_CORE_LCD) U5.R11(VDDS_OSC)
VDD_RTC: C104.1 U5.D6(CAP_VDD_RTC)
VDDS: C80.1 C81.1 C82.1 C83.1 C84.1 C85.1 R8.2 R9.1 U5.E6(VDDS1) U5.E14(VDDS2) U5.F9(VDDS3) U5.K13(VDDS4) U5.N6(VDDS5) U5.P9(VDDS6) U5.P14(VDDS7)
VDDS_DDR: C9.2 C95.2 C96.2 C97.1 C98.1 C99.1 C100.1 C101.1 C102.1 C103.1 C107.1 C108.1 C109.1 C110.1 C111.1 C112.1 C113.1 C114.1 C115.1 C116.1 C117.1 C118.2 C119.1 C120.1 C121.1 C122.2 R6.2 R97.1 R98.1 U5.E5(VDDS_DDR1) U5.F5(VDDS_DDR2) U5.G5(VDDS_DDR3) U5.H5(VDDS_DDR4) U5.J5(VDDS_DDR5) U5.K5(VDDS_DDR6) U5.L5(VDDS_DDR7) U12.A1(VDDQ1) U12.A8(VDDQ2) U12.B2(VDD1) U12.C1(VDDQ3) U12.C9(VDDQ4) U12.D2(VDDQ5) U12.D9(VDD9) U12.E9(VDDQ7) U12.F1(VDDQ8) U12.G7(VDD2) U12.H2(VDDQ9) U12.H9(VDDQ10) U12.K2(VDD4) U12.K8(VDD5) U12.N1(VDD6) U12.N9(VDD7) U12.R1(VDD8) U12.R9(VDD3)
AIN0: P9.39(20) ; also on sheet 9
AIN1: P9.40(45) ; also on sheet 9
AIN2: P9.37(19) ; also on sheet 9
AIN3: P9.38(44) ; also on sheet 9
AIN4: P9.33(17) ; also on sheet 9
AIN5: P9.36(43) ; also on sheet 9
AIN6: P9.35(18) ; also on sheet 9
CAP_VBB_MPU: C91.1 U5.C10(CAP_VBB_MPU)
CAP_VDD_SRAM_CORE: C89.1 U5.D9(CAP_VDD_SRAM_CORE)
CAP_VDD_SRAM_MPU: C90.1 U5.D11(CAP_VDD_SRAM_MPU)
CLKOUT2: P9.41(21) ; also on sheet 10
DDR_A0: U12.N3(A0) ; also on sheet 10
DDR_A1: U12.P7(A1) ; also on sheet 10
DDR_A2: U12.P3(A2) ; also on sheet 10
DDR_A3: U12.N2(A3) ; also on sheet 10
DDR_A4: U12.P8(A4) ; also on sheet 10
DDR_A5: U12.P2(A5) ; also on sheet 10
DDR_A6: U12.R8(A6) ; also on sheet 10
DDR_A7: U12.R2(A7) ; also on sheet 10
DDR_A8: U12.T8(A8) ; also on sheet 10
DDR_A9: U12.R3(A9) ; also on sheet 10
DDR_A10: U12.L7(A10) ; also on sheet 10
DDR_A11: U12.R7(A11) ; also on sheet 10
DDR_A12: U12.N7(A12) ; also on sheet 10
DDR_A13: U12.T3(A13) ; also on sheet 10
DDR_A14: U12.T7(A14) ; also on sheet 10
DDR_A15: U12.M7(A15) ; also on sheet 10
DDR_BA0: U12.M2(BA0) ; also on sheet 10
DDR_BA1: U12.N8(BA1) ; also on sheet 10
DDR_BA2: U12.M3(BA2) ; also on sheet 10
DDR_CASn: U12.K3(CASn) ; also on sheet 10
DDR_CKE: R96.2 U12.K9(CKE) ; also on sheet 10
DDR_CLK: U12.J7(CK) ; also on sheet 10
DDR_CLKn: U12.K7(CKn) ; also on sheet 10
DDR_CSn: U12.L2(CSn) ; also on sheet 10
DDR_D0: U12.E3(DQ0) ; also on sheet 10
DDR_D1: U12.F7(DQ1) ; also on sheet 10
DDR_D2: U12.F2(DQ2) ; also on sheet 10
DDR_D3: U12.F8(DQ3) ; also on sheet 10
DDR_D4: U12.H3(DQ4) ; also on sheet 10
DDR_D5: U12.H8(DQ5) ; also on sheet 10
DDR_D6: U12.G2(DQ6) ; also on sheet 10
DDR_D7: U12.H7(DQ7) ; also on sheet 10
DDR_D8: U12.D7(DQ8) ; also on sheet 10
DDR_D9: U12.C3(DQ9) ; also on sheet 10
DDR_D10: U12.C8(DQ10) ; also on sheet 10
DDR_D11: U12.C2(DQ11) ; also on sheet 10
DDR_D12: U12.A7(DQ12) ; also on sheet 10
DDR_D13: U12.A2(DQ13) ; also on sheet 10
DDR_D14: U12.B8(DQ14) ; also on sheet 10
DDR_D15: U12.A3(DQ15) ; also on sheet 10
DDR_DQM0: U12.E7(LDM) ; also on sheet 10
DDR_DQM1: U12.D3(UDM) ; also on sheet 10
DDR_DQS0: U12.F3(LDQS) ; also on sheet 10
DDR_DQS1: U12.C7(UDQS) ; also on sheet 10
DDR_DQSN0: U12.G3(LDQSn) ; also on sheet 10
DDR_DQSN1: U12.B7(UDQSn) ; also on sheet 10
DDR_ODT: U12.K1(ODT) ; also on sheet 10
DDR_RASn: U12.J3(RASn) ; also on sheet 10
DDR_RESETn: R97.2 U12.T2(RESET#) ; also on sheet 10
DDR_VREF: C123.1 C124.1 R98.2 R100.1 U12.H1(VREF_DQ) U12.M8(VREF_CA) ; also on sheet 10
DDR_WEn: U12.L3(WEn) ; also on sheet 10
EHRPWM1A: P9.14(32) ; also on sheet 10
EHRPWM1B: P9.16(33) ; also on sheet 10
EHRPWM2A: P8.19(10) ; also on sheet 10
EHRPWM2B: P8.13(7) ; also on sheet 10
eMMC_RSTn: R111.2 U13.K5(~{RST}) ; also on sheet 10
eMMC_VCCI: C125.1 U13.C2(VCCI)
ENZ_KALDO_1P8V: R54.2 U5.B4(ENZ_KALDO_1P8V)
GPIO0_7: P9.42(46) ; also on sheet 9
GPIO0_26: P8.14(32) ; also on sheet 10
GPIO0_27: P8.17(9) ; also on sheet 10
GPIO1_12: P8.12(31) ; also on sheet 10
GPIO1_13: P8.11(6) ; also on sheet 10
GPIO1_14: P8.16(33) ; also on sheet 10
GPIO1_15: P8.15(8) ; also on sheet 10
GPIO1_16: P9.15(8) ; also on sheet 10
GPIO1_17: P9.23(12) ; also on sheet 10
GPIO1_28: P9.12(31) ; also on sheet 10
GPIO1_29: P8.26(38) ; also on sheet 10
GPIO2_1: P8.18(34) ; also on sheet 10
GPIO3_19: P9.27(14) ; also on sheet 9
GPIO3_21: P9.25(13) ; also on sheet 9 10
I2C0_SCL: R3.2 U2.28(SCL) U7.1(SCL) ; also on sheet 9
I2C0_SDA: R4.2 U2.27(SDA) U7.3(SDA) ; also on sheet 9
I2C1_SCL: P9.17(9) ; also on sheet 9
I2C1_SDA: P9.18(34) ; also on sheet 9
I2C2_SCL: J4.1 P9.19(10) R177.2 ; also on sheet 9
I2C2_SDA: J4.2 P9.20(35) R178.2 ; also on sheet 9
LCD_DATA0: P8.45(23) R70.2 R95.1 ; also on sheet 9
LCD_DATA1: P8.46(48) R69.2 R94.1 ; also on sheet 9
LCD_DATA2: P8.43(22) R68.2 R75.1 R93.1 ; also on sheet 9
LCD_DATA3: P8.44(47) R67.2 R92.1 ; also on sheet 9
LCD_DATA4: P8.41(21) R66.2 R91.1 ; also on sheet 9
LCD_DATA5: P8.42(46) R65.2 R90.1 ; also on sheet 9
LCD_DATA6: P8.39(20) R64.2 R89.1 ; also on sheet 9
LCD_DATA7: P8.40(45) R63.2 R88.1 ; also on sheet 9
LCD_DATA8: P8.37(19) R62.2 R87.1 ; also on sheet 9
LCD_DATA9: P8.38(44) R61.2 R86.1 ; also on sheet 9
LCD_DATA10: P8.36(43) R60.2 R85.1 ; also on sheet 9
LCD_DATA11: P8.34(42) R59.2 R84.1 ; also on sheet 9
LCD_DATA12: P8.35(18) R58.2 R83.1 ; also on sheet 9
LCD_DATA13: P8.33(17) R57.2 R82.1 ; also on sheet 9
LCD_DATA14: P8.31(16) R56.2 R81.1 ; also on sheet 9
LCD_DATA15: P8.32(41) R55.2 R80.1 ; also on sheet 9
LCD_DE: P8.30(40) ; also on sheet 9
LCD_HSYNC: P8.29(15) ; also on sheet 9
LCD_PCLK: P8.28(39) ; also on sheet 9
LCD_VSYNC: P8.27(14) ; also on sheet 9
LDO_PGOOD: U2.46(LDO_PGOOD) ; also on sheet 10
LEDAA: D2.2(A) R72.2
LEDAC: D2.1(C) Q1.6(3)
LEDBA: D3.2(A) R73.2
LEDBC: D3.1(C) Q1.3
LEDCA: D4.2(A) R74.2
LEDCC: D4.1(C) Q2.6(3)
LEDDA: D5.2(A) R71.2
LEDDC: D5.1(C) Q2.3
MMC0_CD: P10.10(SW_B) R157.1 ; also on sheet 9 10
MMC0_CLKO: R16.1 ; also on sheet 10
MMC0_CMD: R15.1 ; also on sheet 10
MMC0_DAT0: R21.1 ; also on sheet 10
MMC0_DAT1: R31.1 ; also on sheet 10
MMC0_DAT2: R2.1 ; also on sheet 10
MMC0_DAT3: R13.1 ; also on sheet 10
MMC1_CLK: P8.21(11) R110.2 U13.M6(CLK) ; also on sheet 10
MMC1_CMD: P8.20(35) R109.2 U13.M5(CMD) ; also on sheet 10
MMC1_DAT0: P8.25(13) R101.2 U13.A3(DAT0) ; also on sheet 10
MMC1_DAT1: P8.24(37) R102.2 U13.A4(DAT1) ; also on sheet 10
MMC1_DAT2: P8.5(3) R103.2 U13.A5(DAT2) ; also on sheet 10
MMC1_DAT3: P8.6(28) R104.2 U13.B2(DAT3) ; also on sheet 10
MMC1_DAT4: P8.23(12) R105.2 U13.B3(DAT4) ; also on sheet 10
MMC1_DAT5: P8.22(36) R106.2 U13.B4(DAT5) ; also on sheet 10
MMC1_DAT6: P8.3(2) R107.2 U13.B5(DAT6) ; also on sheet 10
MMC1_DAT7: P8.4(27) R108.2 U13.B6(DAT7) ; also on sheet 10
P_BYPASS: C4.2 U2.47(BYPASS)
P_INT_LDO: C3.2 U2.48(INT_LDO)
P_L1: L1.1 U2.20(L1)
P_L2: L2.1 U2.23(L2)
P_L3: L3.1 U2.31(L3)
PMIC_INT: R1.2 U2.45(INT) ; also on sheet 10
PMIC_PGOOD: U2.26(PGOOD) ; also on sheet 10
PMIC_POWR_EN: U2.9(PWR_EN) ; also on sheet 9
PWR_BUT: P9.9(5) S3.2(B1) S3.4(B2) U2.25(PB_IN)
PWR_LEDR: D1.1(C) R12.2
SD_CLK: C5.1 P10.5(CLOCK) R16.2 R152.2
SD_CMD: P10.3(CMD) R15.2 R151.2
SD_DAT0: P10.7(DAT0) R21.2 R153.2
SD_DAT1: P10.8(DAT1) R31.2 R154.2
SD_DAT2: P10.1(DAT2) R2.2 R150.2
SD_DAT3: P10.2(CD/DAT3) R13.2 R155.2
SPI1_CS0: P9.28(39) ; also on sheet 9
SPI1_D0: P9.29(15) ; also on sheet 9
SPI1_D1: P9.30(40) ; also on sheet 9
SPI1_SCLK: P9.31(16) ; also on sheet 9
SYS_5V: C7.2 C8.2 C10.2 C13.2 C17.1 P9.7(4) P9.8(29) R71.1 R72.1 R73.1 R74.1 U2.2(VINLDO) U2.7(SYS1) U2.8(SYS2) U2.21(VIN_DCDC1) U2.22(VIN_DCDC2) U2.32(VIN_DCDC3) U2.39(LDO3_IN) U2.42(LDO4_IN) U4.2(IN) ; also on sheet 9
SYS_RESETn: P9.10(30) ; also on sheet 8 10
TESTOUT: TP3.1(TP) U5.A3(TESTOUT)
TIMER4: P8.7(4) ; also on sheet 10
TIMER5: P8.9(5) ; also on sheet 10
TIMER6: P8.10(30) ; also on sheet 10
TIMER7: P8.8(29) ; also on sheet 10
UART1_RXD: P9.26(38) ; also on sheet 9
UART1_TXD: P9.24(37) ; also on sheet 9
UART2_RXD: J5.1 P9.22(36) ; also on sheet 9
UART2_TXD: J5.2 P9.21(11) ; also on sheet 9
UART4_RXD: P9.11(6) ; also on sheet 10
UART4_TXD: P9.13(7) ; also on sheet 10
USB_DC: C1.2 R168.1 U2.12(USB) ; also on sheet 9
USR0: Q1.2(5) R76.1 ; also on sheet 10
USR1: Q1.5 R77.1 ; also on sheet 10
USR2: Q2.2(5) R78.1 ; also on sheet 10
USR3: Q2.5 R79.1 ; also on sheet 10
VDCDC1: L1.2 R6.1 U2.19(VDCDC1)
VIO: C146.1 R7.2 U2.18(VIO) ; also on sheet 10
VLDO1: R5.1 R7.1 R8.1 U2.3(VLDO1)
VRTC: C16.1 C105.1 R5.2 U5.D7(VDDS_RTC) ; also on sheet 9
WAKEUP: U2.13(WAKEUP) ; also on sheet 9
WP: R156.2 TP4.1(TP) U7.5(WP)
ZQ: R99.2 U12.L8(ZQ)
N21757673: C19.1 R10.1 R11.2 U4.4(ADJ)
N21769115: R75.2 S2.1(A1) S2.3(A2)
N22420400: R173.1 R174.2 TP5.1(TP) U2.4(BAT1) U2.5(BAT2)
N22420444: R174.1 TP6.1(TP) U2.6(BAT_SENSE)
N22420447: TP7.1(TP) U2.11(TS)
N22569088: J5.4 R147.2
N22569092: J4.4 R146.2
N22823317: R175.1 U2.33(ISINK2)
N22823323: R176.1 U2.34(ISINK1)

Not connected (* = marked no-connect by the designer): P10 S2(SHD2)*; U2 14(MUX_IN)* 15(NC)* 16(MUX_OUT)* 17(NC1)* 35(ISET1)* 36(ISET2)* 37(L4)* 38(FB_WLED)* 44(RESET)*; U5 M5(VPP); U12 J1(NC1)* J9(NC2)* L1(NC3)* L9(NC4)*; U13 A1(NC11)* A2(NC4)* A7(NC6)* A8(NC7)* A9(NC18)* A10(NC95)* A11(NC94)* A12(NC93)* A13(NC92)* A14(NC91)* B1(NC90)* B7(NC89)* B8(NC74)* B9(NC53)* B10(NC52)* B11(NC51)* B12(NC50)* B13(NC49)* B14(NC19)* C1(NC34)* C3(NC33)* C5(NC32)* C7(NC31)* C8(NC30)* C9(NC29)* C10(NC25)* C11(NC23)* C12(NC22)* C13(NC21)* C14(NC20)* D1(NC48)* D2(NC46)* D3(NC39)* D4(NC38)* D12(NC37)* D13(NC36)* D14(NC35)* E1(NC1)* E2(NC2)* E3(NC3)* E5(NC121)* E8(NC8)* E9(NC9)* E10(NC10)* E12(NC12)* E13(NC13)* E14(NC14)* F1(NC15)* F2(NC16)* F3(NC17)* F10(NC24)* F12(NC26)* F13(NC27)* F14(NC28)* G1(NC88)* G2(NC81)* G3(NC79)* G10(NC78)* G12(NC40)* G13(NC41)* G14(NC42)* H1(NC43)* H2(NC44)* H3(NC45)* H5(NC47)* H12(NC54)* H13(NC55)* H14(NC56)* J1(NC57)* J2(NC58)* J3(NC59)* J12(NC117)* J13(NC69)* J14(NC70)* K1(NC71)* K2(NC72)* K3(NC73)* K6(NC123)* K7(NC77)* K10(NC80)* K12(NC82)* K13(NC83)* K14(NC84)* L1(NC85)* L2(NC86)* L3(NC87)* L12(NC96)* L13(NC97)* L14(NC98)* M1(NC99)* M2(NC100)* M3(NC101)* M7(NC105)* M8(NC106)* M9(NC107)* M10(NC108)* M11(NC109)* M12(NC110)* M13(NC111)* M14(NC112)* N1(NC113)* N3(NC115)* N6(NC122)* N7(NC118)* N8(NC119)* N9(NC120)* N10(NC75)* N11(NC76)* N12(NC68)* N13(NC67)* N14(NC66)* P1(NC65)* P2(NC64)* P7(NC63)* P8(NC61)* P9(NC62)* P10(NC114)* P11(NC104)* P12(NC103)* P13(NC102)* P14(NC116)*

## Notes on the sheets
sheet 1
- REV
- Description
- DATE
- BY
- PAGE NO.
- SCHEMATIC PAGE
- v1
- First release
  PCB version is v1
- 3/6/2015
- QXN
- 1
- COVER PAGE
- 2
- POWER MANAGEMENT
- v1c
- 1.Changed the SRAM to the MT41K256M16TW-107:P.
  2.Changed the eMMC to the MTFC4GACAJCN-1M WT.
  3.Changed the PCB version to v1c
- 3/22/2016
- QXN
- 3
- PROCESSOR 1 OF 3, JTAG HEADER
- 4
- PROCESSOR 2 OF 3, UAB PORTS
- 1. Page 3: Added series resistor (R32,R33,R37-R44)=33R to the MMC1 lines,
      C6=DNI(10pF) to the MMC1_CLK to DGND;
      Changed C24 from 2.2uF to 100nF; Changed C30 from   100nF to DNI;
      Add D6 and D7 to Reset lines ; Removed U17.
- 5
- PROCESSOR 3 OF 3
- 6
- LED, CONFIGURATION AND BUTTON
- v1.1
- 2. Page 4: Changed USB1_VBUS series resistor from FB8=0.1R 0805 to R36=0R 0402.
- 3. Page 8: Connected the Pin A6 J5 of U13(eMMC IC) to DGND.
- 7
- DDR3 MEMORY
- FJN
- 4. Page 9: Added AM3358 GPIO1_8 and a Positive-AND gate(U1) to reset ethernet LAN8710A;
- 5/24/2021
- 8
- eMMC FLASH
- Added series resistor (R149,R158,R166,R171,R172)=33R to the LAN8710A TX lines;
- 5.Page 10: Changed MicroSD Connector from ALPS_SCHA5B0200 to YULIANG_YL004-030-001;
      Added series resistor (R2,R13,R15,R16,R21,R31)=33R,     C5=DNI(10pF) to the MMC0 lines.
- 9
- 10/100 ETHERNET
- 6. The PCB Revision for this board is Rev v1.1.
- 10
- EXP CONN, uSD
- 1.Change PCB Seeed Logo.
- v1.2
- 2.Modify PCB Version to v1.2
- 8/11/2022
- LZB
- 1.Page3:Change Y2 to the M24000J407;
               Change C25,C26 from 18pF to 27pF;
               Change Y4 to the DS24576007.
- 8/16/2024
- YHB
- v1.2
- This work is licensed under the Creative Commons Attribution 4.0 International License.
  To view a copy of this license,visit
  http://creativecommons.org/licenses/by-sa/4.0
- This schematic is  *NOT SUPPORTED* and DOES NOT constitute
  a reference design. Only Community support is allowed via
  resources at BeagleBoard.org/discuss.
  THERE IS NO WARRANTY FOR THIS DESIGN , TO THE EXTENT
  PERMITTED BY APPLICABLE LAW. EXCEPT WHEN OTHERWISE STATED
  IN WRITING THE COPYRIGHT HOLDERS AND/OR OTHER PARTIES
  PROVIDE THE DESIGN IS WITHOUT WARRANTY OF ANY KIND, EITHER
  EXPRESSED OR IMPLIED, INCLUDING, BUT NOT LIMITED TO, THE
  IMPLIED WARRANTIES OF MERCHANTABILITY AND FITNESS FOR A
  PARTICULAR PURPOSE. THE ENTIRE RISK AS TO THE QUALITY AND
  PERFORMANCE OF THE DESIGN IS WITH YOU. SHOULD THE DESIGN
  PROVE DEFECTIVE, YOU ASSUME THE COST OF ALL NECESSARY
  SERVICING, REPAIR OR CORRECTION.
sheet 2
- Battery access pins.
  Pins are randomly
  placed to fit them in,
  but will be able to tie
  into them either with a
  cape or wires. Pins will
  not be populated.
- select wether the
  usb can provide1A
  current power
- POWER BUTTON
- 1.5V
- POWER LED
- 500mA
sheet 3
- SYS_BOOT0
- SYS_BOOT1
- uSD BOOT
- USR0
- USR1
- USR2
- USR3
- SYS_BOOT2
- SYS_BOOT3
- SYS_BOOT4
- SYS_BOOT5
- User LED's
- SYS_BOOT6
- SYS_BOOT7
- SYS_BOOT8
- SYS_BOOT9
- SYS_BOOT10
- SYS_BOOT11
- SYS_BOOT12
- SYS_BOOT13
- SYS_BOOT14
- SYS_BOOT15
- Boot Configuration
sheet 4
- DDR3L SDRAM
- MT41K256M16TW-107:P
- D2516EC4BXGGB
- 4Gb DDR3
sheet 5
- MTFC4GACAAAM-1M WT
- KE4CN2H5A-A58
- MTFC4GACAJCN-1M WT
sheet 6
- CAUTION: USED ON BOARD
- CAUTION: USED ON BOARD
- EXPANSION HEADER
- EXPANSION HEADER
- Board ID
- Layout Note:
- Place R16,C5 Close To MPU.
- 256KX8
- Layout Note:
- uSD CONNECTOR
- Place R16,C5 Close To MPU.
- GROVE CONNECTOR
